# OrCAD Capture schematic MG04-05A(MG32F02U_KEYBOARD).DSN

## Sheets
1 01. Power Supply: size B; title: System Power; rev: 1.1; company: megawin; note: MG04-05
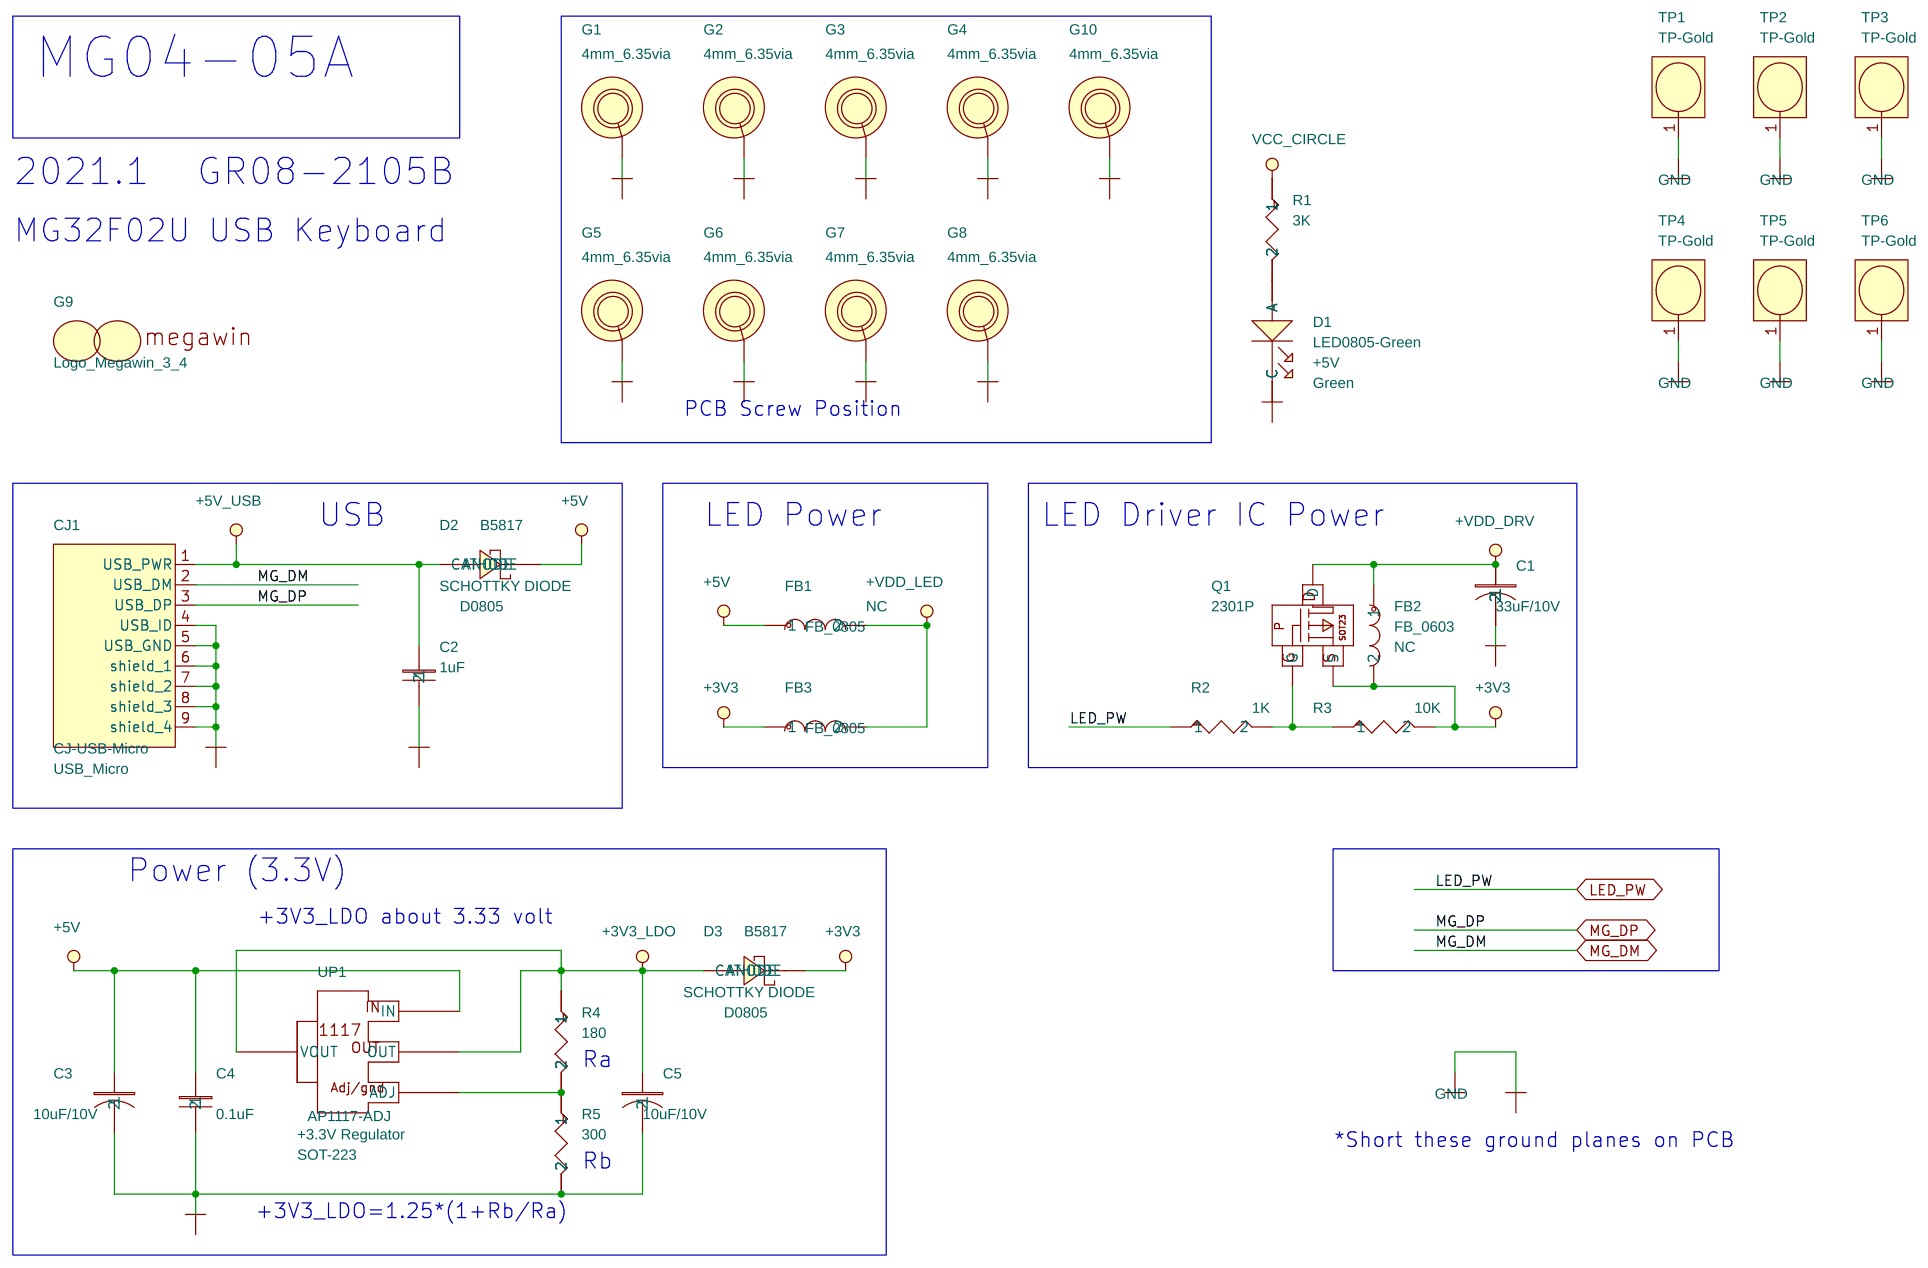
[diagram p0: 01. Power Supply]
2 02. Key Matrix: size Custom; title: Key Matrix; rev: 1.0
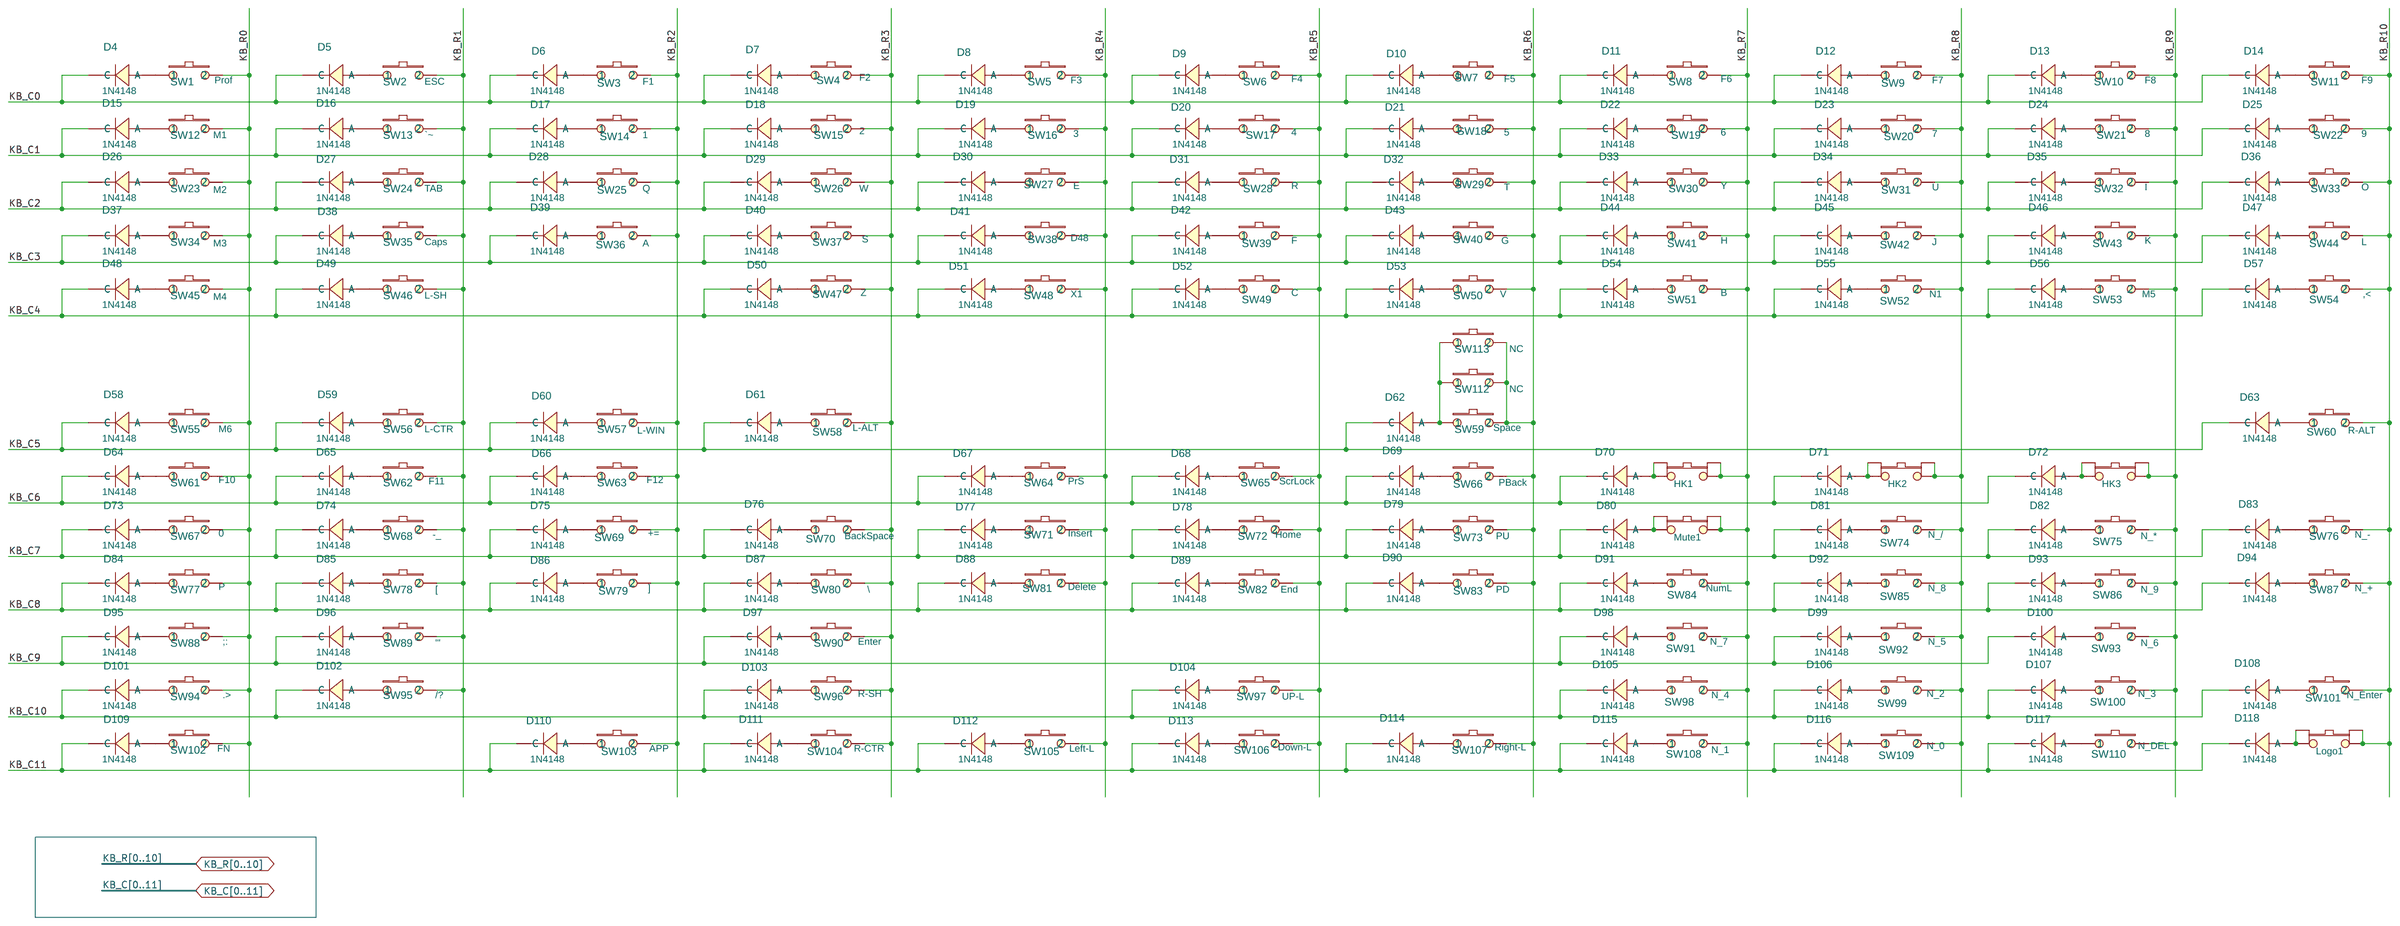
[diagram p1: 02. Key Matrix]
3 03. LED Matrix: size Custom; title: LED Matrix; rev: 1.0
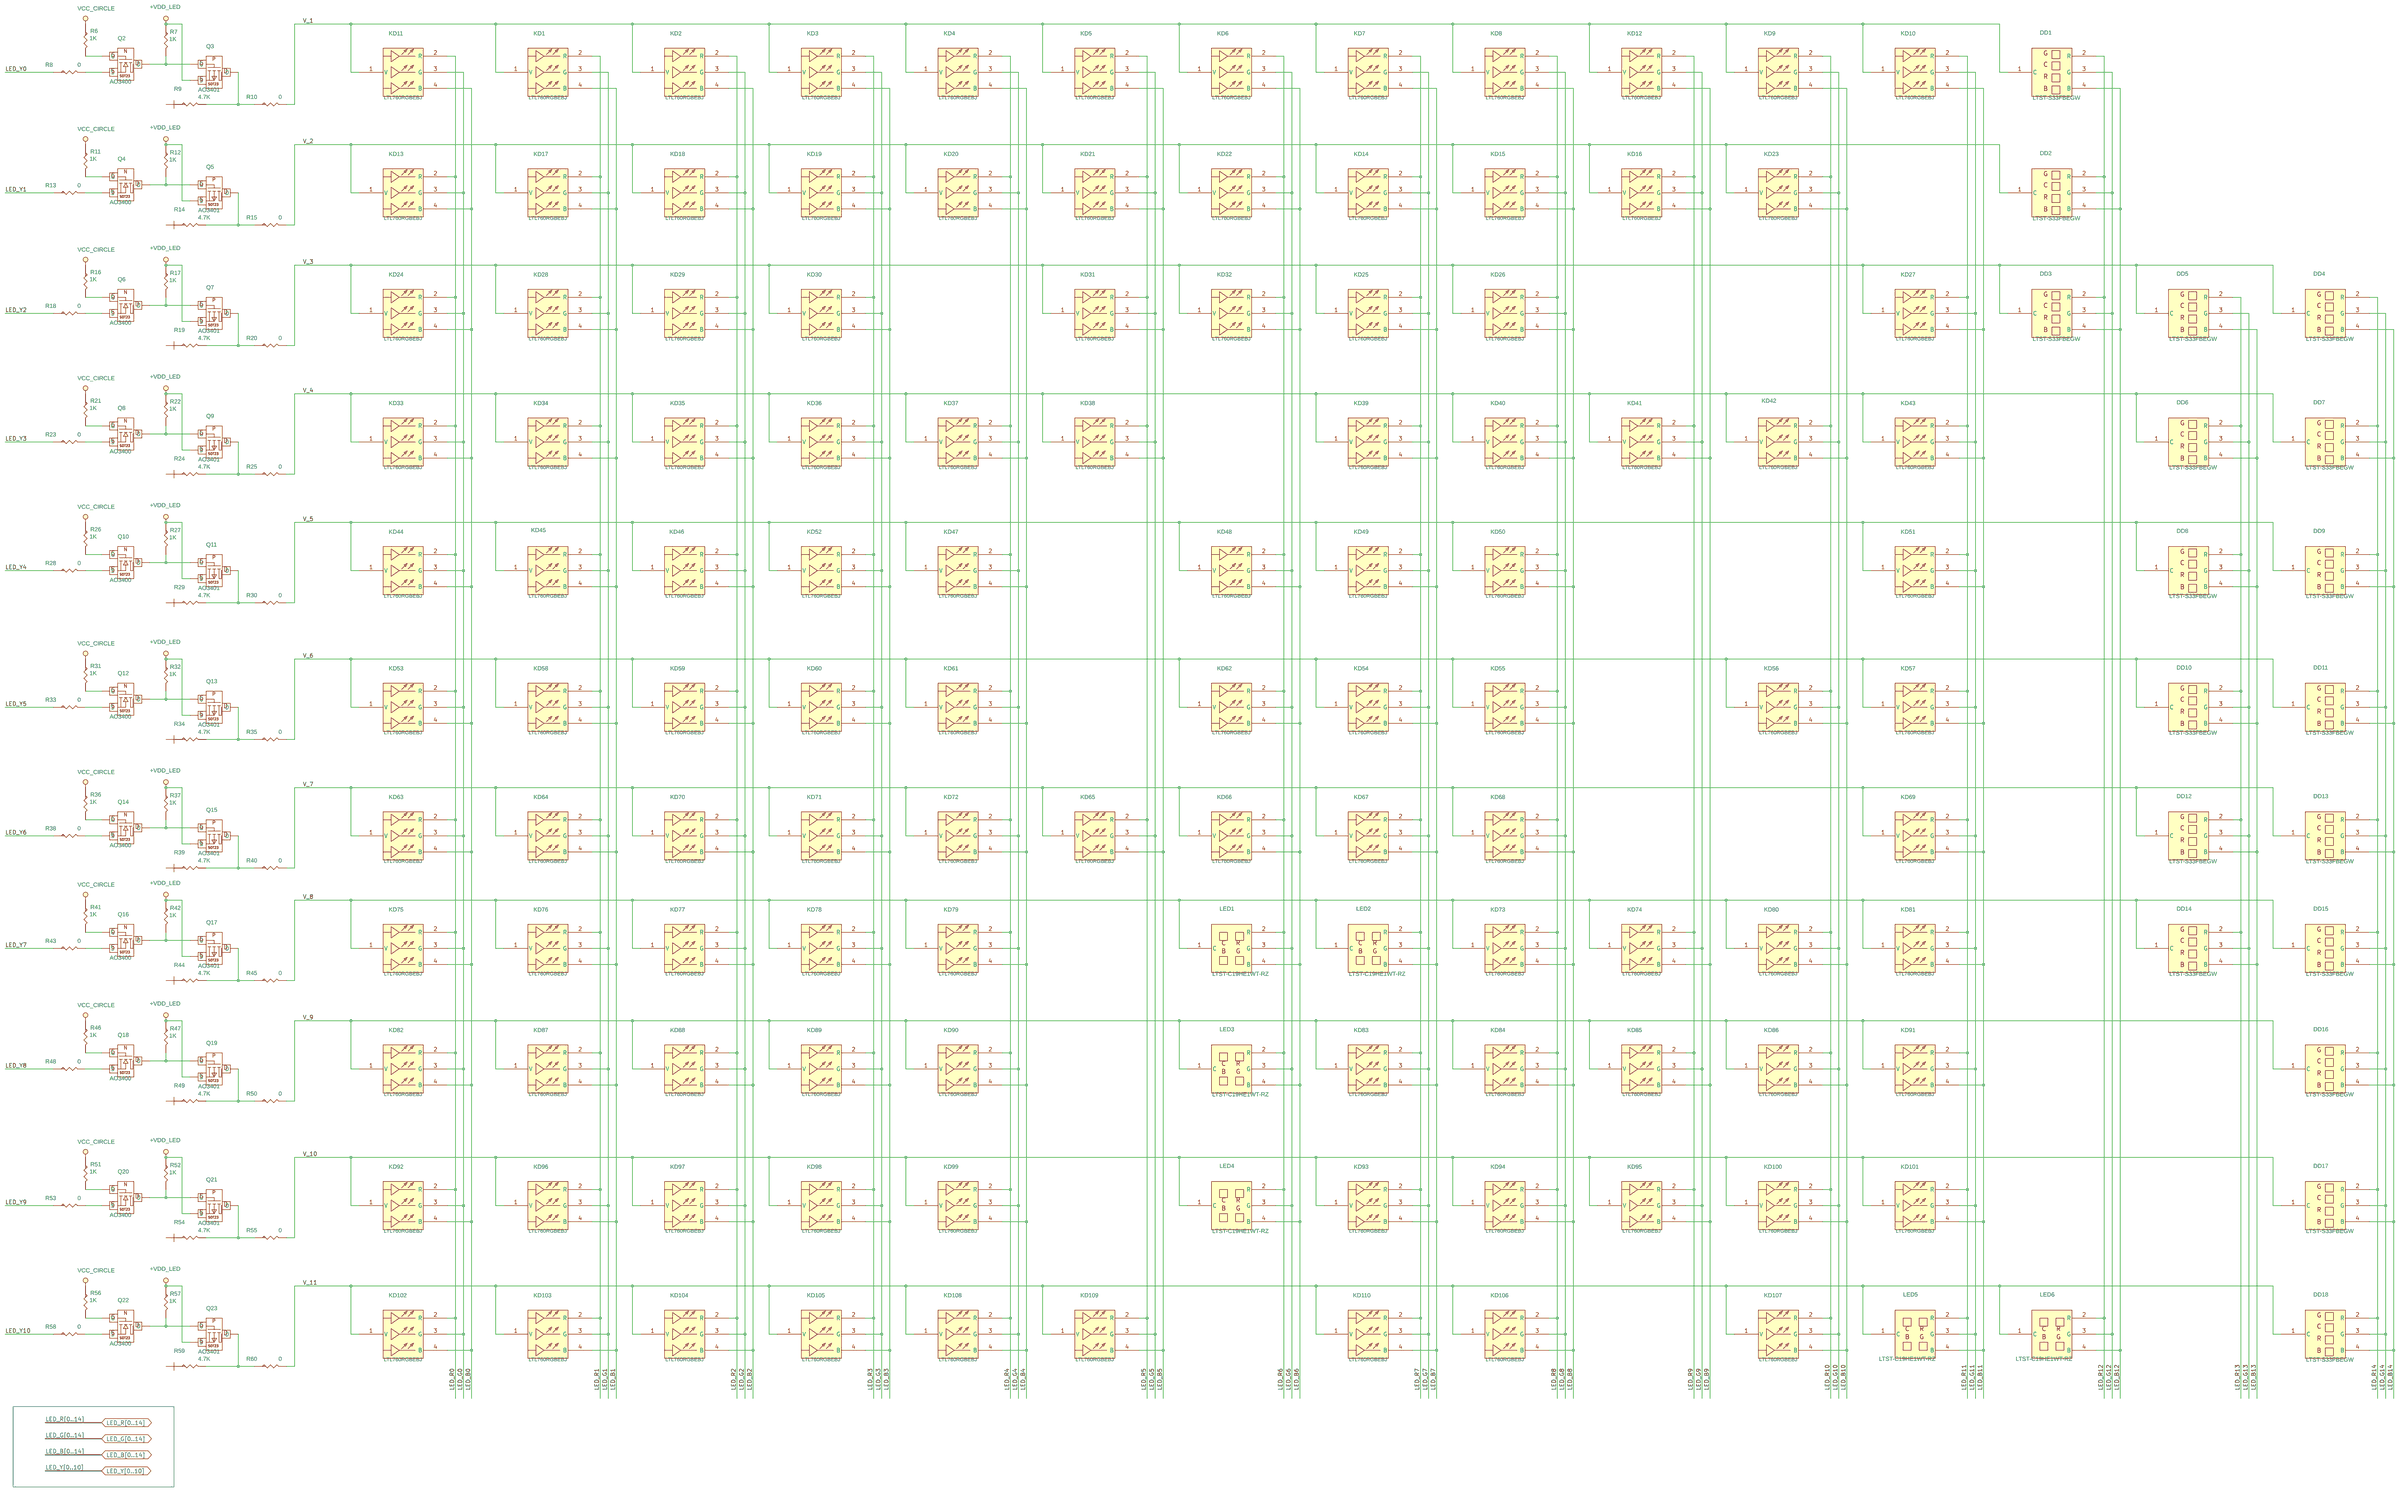
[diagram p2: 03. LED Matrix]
4 04. MCU IF: size Custom; title: MCU IF, LED Driver and Others
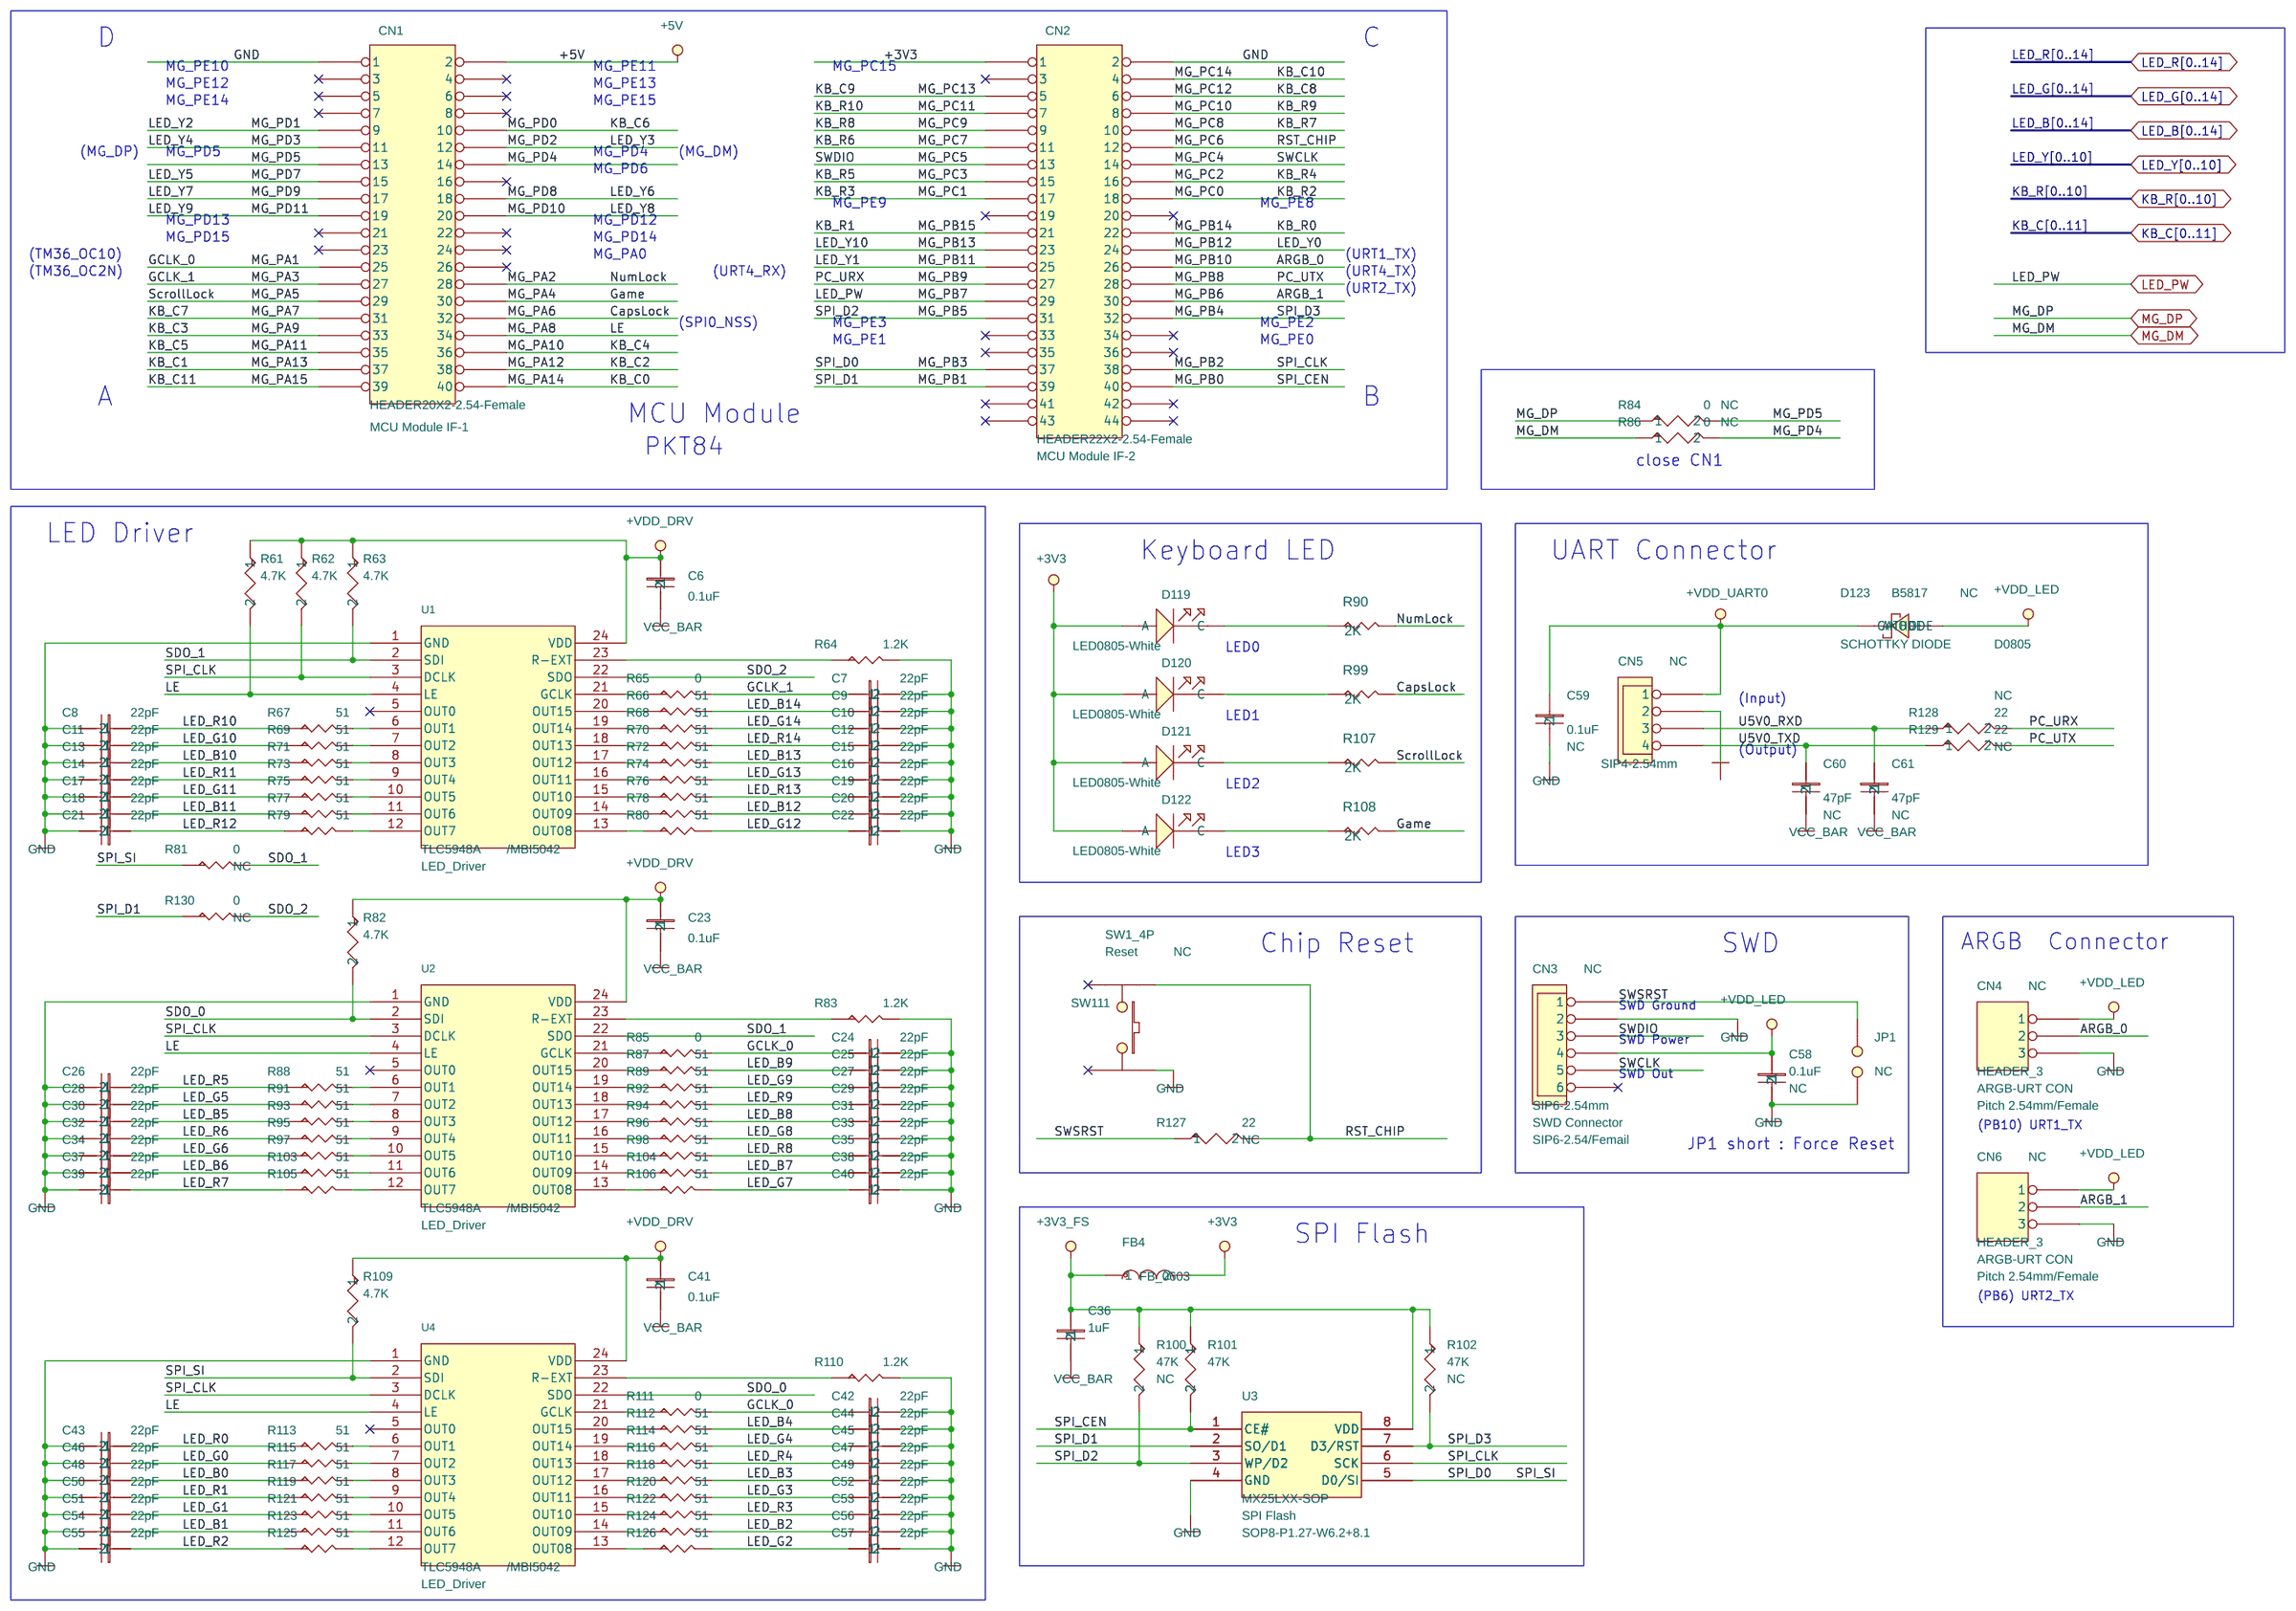
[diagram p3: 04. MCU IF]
5 20. Board Comment: title: Board Comment; rev: 1.0
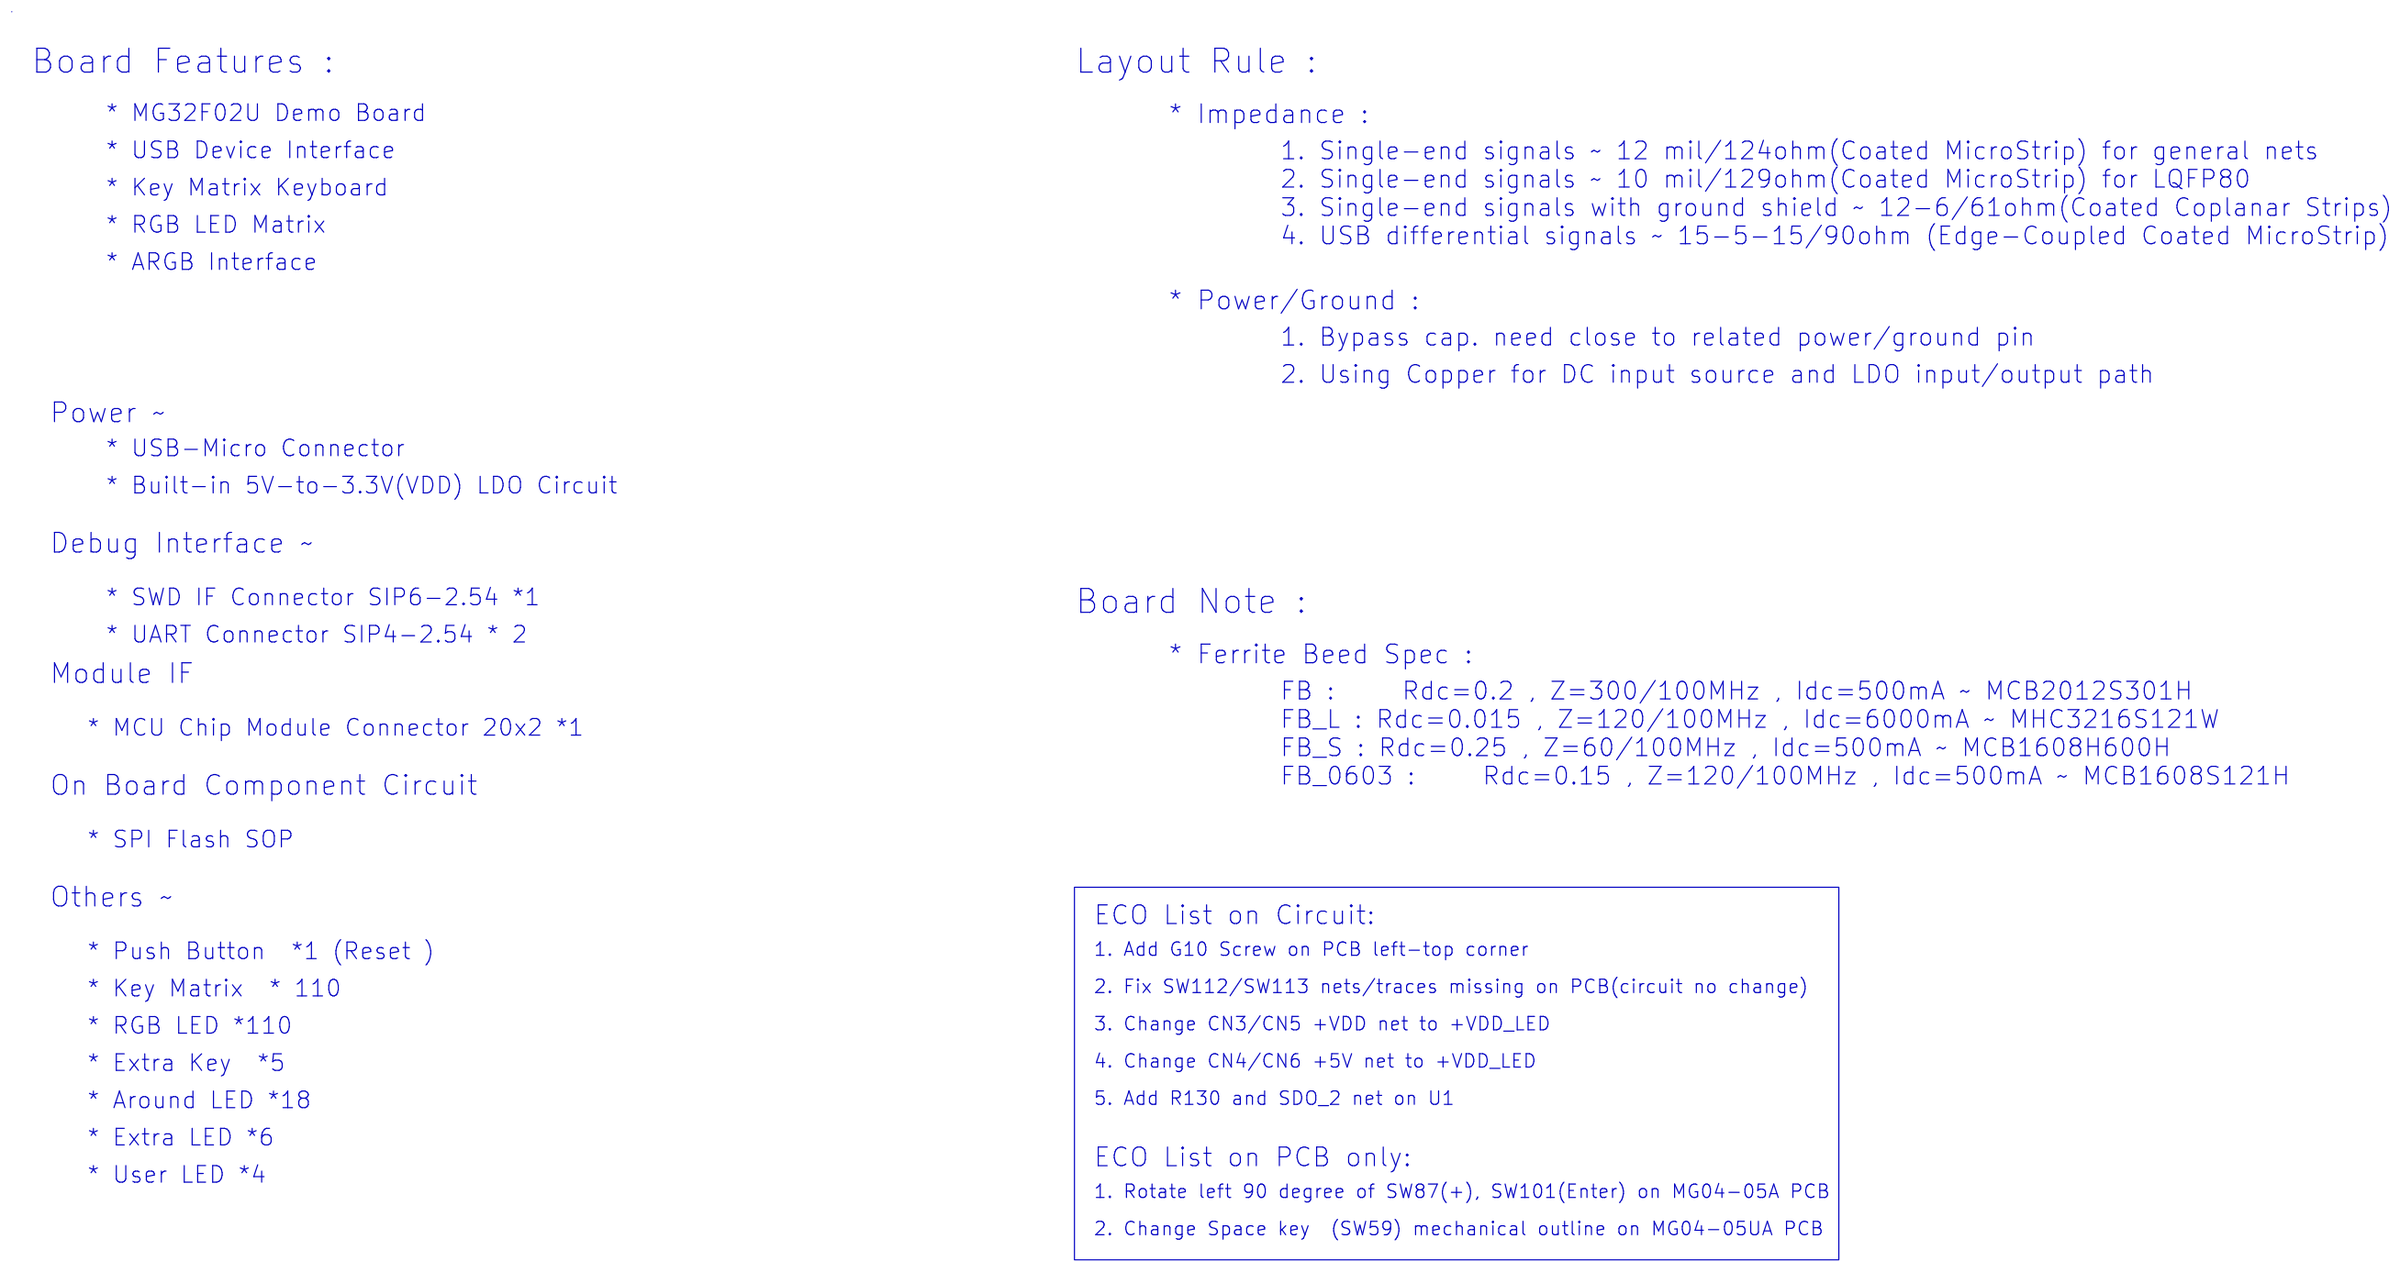
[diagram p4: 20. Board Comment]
6 21. PCB Placement: title: PCB Placement Plan; rev: 1.0
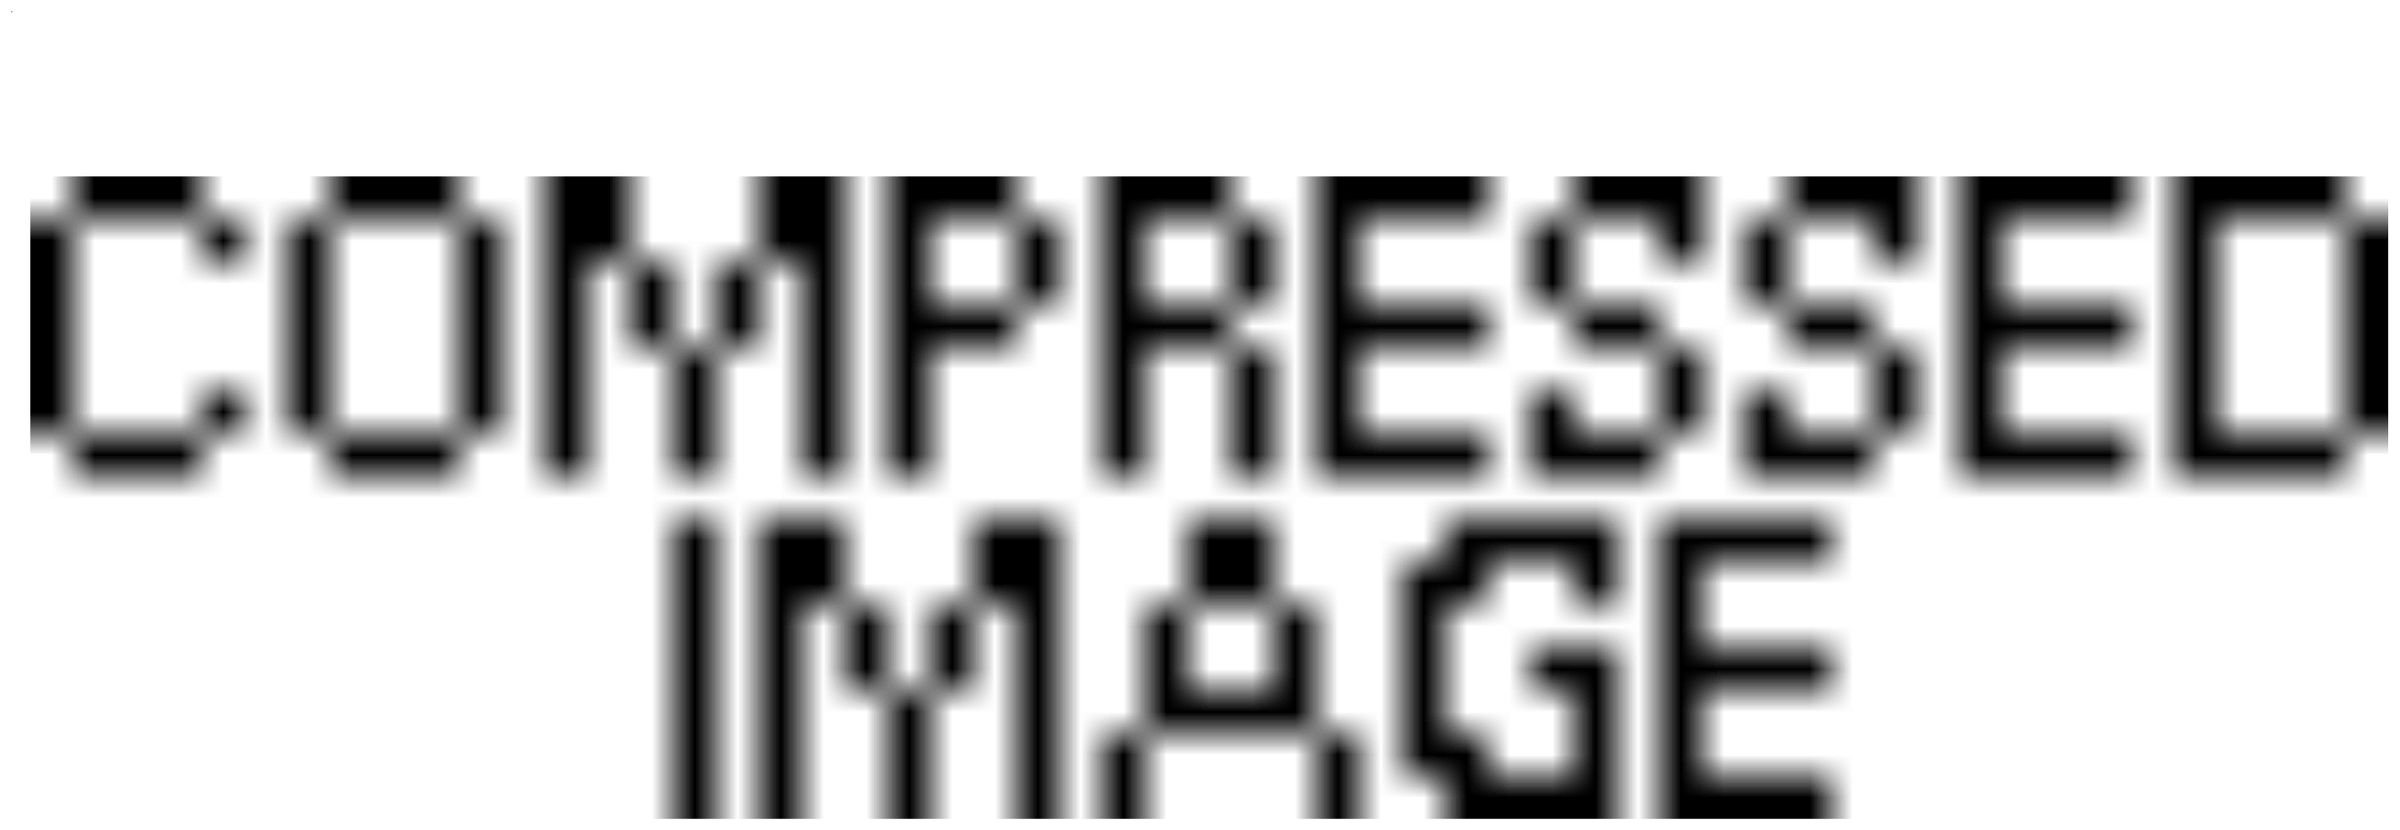
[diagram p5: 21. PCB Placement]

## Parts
sheet 01. Power Supply
C1  33uF/10V  [C-0805]
C2  1uF  [C-0603]
C3  10uF/10V  [C-0805]
C4  0.1uF  [C-0603]
C5  10uF/10V  [C-0805]
CJ1  CJ-USB-Micro  [USB5A-MICRO-290X220P065]
D1  LED0805-Green  [LED-0805]
D2  B5817  [D-0805]
D3  B5817  [D-0805]
FB1  FB_0805  [L-0805]
FB2  FB_0603  [L-0603]
FB3  FB_0805  [L-0805]
G1  4mm_6.35via  [SCREW1-H4-R6.35]
G2  4mm_6.35via  [SCREW1-H4-R6.35]
G3  4mm_6.35via  [SCREW1-H4-R6.35]
G4  4mm_6.35via  [SCREW1-H4-R6.35]
G5  4mm_6.35via  [SCREW1-H4-R6.35]
G6  4mm_6.35via  [SCREW1-H4-R6.35]
G7  4mm_6.35via  [SCREW1-H4-R6.35]
G8  4mm_6.35via  [SCREW1-H4-R6.35]
G9  Logo_Megawin_3_4  [MEGAWIN_3.4]
G10  4mm_6.35via  [SCREW1-H4-R6.35]
Q1  2301P  [SOT-23]
R1  3K  [R-0603]
R2  1K  [R-0603]
R3  10K  [R-0603]
R4  180  [R-0603]
R5  300  [R-0603]
TP1  TP-Gold  [SIP1-39]
TP2  TP-Gold  [SIP1-39]
TP3  TP-Gold  [SIP1-39]
TP4  TP-Gold  [SIP1-39]
TP5  TP-Gold  [SIP1-39]
TP6  TP-Gold  [SIP1-39]
UP1  AP1117-ADJ  [SOT223H\3P]
sheet 02. Key Matrix
D4  1N4148  [DIODE_DO213AA]
D5  1N4148  [DIODE_DO213AA]
D6  1N4148  [DIODE_DO213AA]
D7  1N4148  [DIODE_DO213AA]
D8  1N4148  [DIODE_DO213AA]
D9  1N4148  [DIODE_DO213AA]
D10  1N4148  [DIODE_DO213AA]
D11  1N4148  [DIODE_DO213AA]
D12  1N4148  [DIODE_DO213AA]
D13  1N4148  [DIODE_DO213AA]
D14  1N4148  [DIODE_DO213AA]
D15  1N4148  [DIODE_DO213AA]
D16  1N4148  [DIODE_DO213AA]
D17  1N4148  [DIODE_DO213AA]
D18  1N4148  [DIODE_DO213AA]
D19  1N4148  [DIODE_DO213AA]
D20  1N4148  [DIODE_DO213AA]
D21  1N4148  [DIODE_DO213AA]
D22  1N4148  [DIODE_DO213AA]
D23  1N4148  [DIODE_DO213AA]
D24  1N4148  [DIODE_DO213AA]
D25  1N4148  [DIODE_DO213AA]
D26  1N4148  [DIODE_DO213AA]
D27  1N4148  [DIODE_DO213AA]
D28  1N4148  [DIODE_DO213AA]
D29  1N4148  [DIODE_DO213AA]
D30  1N4148  [DIODE_DO213AA]
D31  1N4148  [DIODE_DO213AA]
D32  1N4148  [DIODE_DO213AA]
D33  1N4148  [DIODE_DO213AA]
D34  1N4148  [DIODE_DO213AA]
D35  1N4148  [DIODE_DO213AA]
D36  1N4148  [DIODE_DO213AA]
D37  1N4148  [DIODE_DO213AA]
D38  1N4148  [DIODE_DO213AA]
D39  1N4148  [DIODE_DO213AA]
D40  1N4148  [DIODE_DO213AA]
D41  1N4148  [DIODE_DO213AA]
D42  1N4148  [DIODE_DO213AA]
D43  1N4148  [DIODE_DO213AA]
D44  1N4148  [DIODE_DO213AA]
D45  1N4148  [DIODE_DO213AA]
D46  1N4148  [DIODE_DO213AA]
D47  1N4148  [DIODE_DO213AA]
D48  1N4148  [DIODE_DO213AA]
D49  1N4148  [DIODE_DO213AA]
D50  1N4148  [DIODE_DO213AA]
D51  1N4148  [DIODE_DO213AA]
D52  1N4148  [DIODE_DO213AA]
D53  1N4148  [DIODE_DO213AA]
D54  1N4148  [DIODE_DO213AA]
D55  1N4148  [DIODE_DO213AA]
D56  1N4148  [DIODE_DO213AA]
D57  1N4148  [DIODE_DO213AA]
D58  1N4148  [DIODE_DO213AA]
D59  1N4148  [DIODE_DO213AA]
D60  1N4148  [DIODE_DO213AA]
D61  1N4148  [DIODE_DO213AA]
D62  1N4148  [DIODE_DO213AA]
D63  1N4148  [DIODE_DO213AA]
D64  1N4148  [DIODE_DO213AA]
D65  1N4148  [DIODE_DO213AA]
D66  1N4148  [DIODE_DO213AA]
D67  1N4148  [DIODE_DO213AA]
D68  1N4148  [DIODE_DO213AA]
D69  1N4148  [DIODE_DO213AA]
D70  1N4148  [DIODE_DO213AA]
D71  1N4148  [DIODE_DO213AA]
D72  1N4148  [DIODE_DO213AA]
D73  1N4148  [DIODE_DO213AA]
D74  1N4148  [DIODE_DO213AA]
D75  1N4148  [DIODE_DO213AA]
D76  1N4148  [DIODE_DO213AA]
D77  1N4148  [DIODE_DO213AA]
D78  1N4148  [DIODE_DO213AA]
D79  1N4148  [DIODE_DO213AA]
D80  1N4148  [DIODE_DO213AA]
D81  1N4148  [DIODE_DO213AA]
D82  1N4148  [DIODE_DO213AA]
D83  1N4148  [DIODE_DO213AA]
D84  1N4148  [DIODE_DO213AA]
D85  1N4148  [DIODE_DO213AA]
D86  1N4148  [DIODE_DO213AA]
D87  1N4148  [DIODE_DO213AA]
D88  1N4148  [DIODE_DO213AA]
D89  1N4148  [DIODE_DO213AA]
D90  1N4148  [DIODE_DO213AA]
D91  1N4148  [DIODE_DO213AA]
D92  1N4148  [DIODE_DO213AA]
D93  1N4148  [DIODE_DO213AA]
D94  1N4148  [DIODE_DO213AA]
D95  1N4148  [DIODE_DO213AA]
D96  1N4148  [DIODE_DO213AA]
D97  1N4148  [DIODE_DO213AA]
D98  1N4148  [DIODE_DO213AA]
D99  1N4148  [DIODE_DO213AA]
D100  1N4148  [DIODE_DO213AA]
D101  1N4148  [DIODE_DO213AA]
D102  1N4148  [DIODE_DO213AA]
D103  1N4148  [DIODE_DO213AA]
D104  1N4148  [DIODE_DO213AA]
D105  1N4148  [DIODE_DO213AA]
D106  1N4148  [DIODE_DO213AA]
D107  1N4148  [DIODE_DO213AA]
D108  1N4148  [DIODE_DO213AA]
D109  1N4148  [DIODE_DO213AA]
D110  1N4148  [DIODE_DO213AA]
D111  1N4148  [DIODE_DO213AA]
D112  1N4148  [DIODE_DO213AA]
D113  1N4148  [DIODE_DO213AA]
D114  1N4148  [DIODE_DO213AA]
D115  1N4148  [DIODE_DO213AA]
D116  1N4148  [DIODE_DO213AA]
D117  1N4148  [DIODE_DO213AA]
D118  1N4148  [DIODE_DO213AA]
HK1  SW-PB-4P  [SW-TACT-P4.5X6.5-Z6.2X6.2X5]
HK2  SW-PB-4P  [SW-TACT-P4.5X6.5-Z6.2X6.2X5]
HK3  SW-PB-4P  [SW-TACT-P4.5X6.5-Z6.2X6.2X5]
Logo1  SW-PB-4P  [SW-TACT-P4.5X6.5-Z6.2X6.2X5]
Mute1  SW-PB-4P  [SW-TACT-P4.5X6.5-Z6.2X6.2X5]
SW1  SW_PB_SPST  [SW2_KS4B]
SW2  SW_PB_SPST  [SW2_KS4B]
SW3  SW_PB_SPST  [SW2_KS4B]
SW4  SW_PB_SPST  [SW2_KS4B]
SW5  SW_PB_SPST  [SW2_KS4B]
SW6  SW_PB_SPST  [SW2_KS4B]
SW7  SW_PB_SPST  [SW2_KS4B]
SW8  SW_PB_SPST  [SW2_KS4B]
SW9  SW_PB_SPST  [SW2_KS4B]
SW10  SW_PB_SPST  [SW2_KS4B]
SW11  SW_PB_SPST  [SW2_KS4B]
SW12  SW_PB_SPST  [SW2_KS4B]
SW13  SW_PB_SPST  [SW2_KS4B]
SW14  SW_PB_SPST  [SW2_KS4B]
SW15  SW_PB_SPST  [SW2_KS4B]
SW16  SW_PB_SPST  [SW2_KS4B]
SW17  SW_PB_SPST  [SW2_KS4B]
SW18  SW_PB_SPST  [SW2_KS4B]
SW19  SW_PB_SPST  [SW2_KS4B]
SW20  SW_PB_SPST  [SW2_KS4B]
SW21  SW_PB_SPST  [SW2_KS4B]
SW22  SW_PB_SPST  [SW2_KS4B]
SW23  SW_PB_SPST  [SW2_KS4B]
SW24  SW_PB_SPST  [SW2_KS4B]
SW25  SW_PB_SPST  [SW2_KS4B]
SW26  SW_PB_SPST  [SW2_KS4B]
SW27  SW_PB_SPST  [SW2_KS4B]
SW28  SW_PB_SPST  [SW2_KS4B]
SW29  SW_PB_SPST  [SW2_KS4B]
SW30  SW_PB_SPST  [SW2_KS4B]
SW31  SW_PB_SPST  [SW2_KS4B]
SW32  SW_PB_SPST  [SW2_KS4B]
SW33  SW_PB_SPST  [SW2_KS4B]
SW34  SW_PB_SPST  [SW2_KS4B]
SW35  SW_PB_SPST  [SW2_KS4B]
SW36  SW_PB_SPST  [SW2_KS4B]
SW37  SW_PB_SPST  [SW2_KS4B]
SW38  SW_PB_SPST  [SW2_KS4B]
SW39  SW_PB_SPST  [SW2_KS4B]
SW40  SW_PB_SPST  [SW2_KS4B]
SW41  SW_PB_SPST  [SW2_KS4B]
SW42  SW_PB_SPST  [SW2_KS4B]
SW43  SW_PB_SPST  [SW2_KS4B]
SW44  SW_PB_SPST  [SW2_KS4B]
SW45  SW_PB_SPST  [SW2_KS4B]
SW46  SW_PB_SPST  [SW2_KS4B]
SW47  SW_PB_SPST  [SW2_KS4B]
SW48  SW_PB_SPST  [SW2_KS4B]
SW49  SW_PB_SPST  [SW2_KS4B]
SW50  SW_PB_SPST  [SW2_KS4B]
SW51  SW_PB_SPST  [SW2_KS4B]
SW52  SW_PB_SPST  [SW2_KS4B]
SW53  SW_PB_SPST  [SW2_KS4B]
SW54  SW_PB_SPST  [SW2_KS4B]
SW55  SW_PB_SPST  [SW2_KS4B]
SW56  SW_PB_SPST  [SW2_KS4B]
SW57  SW_PB_SPST  [SW2_KS4B]
SW58  SW_PB_SPST  [SW2_KS4B]
SW59  SW_PB_SPST  [SW2_KS4B]
SW60  SW_PB_SPST  [SW2_KS4B]
SW61  SW_PB_SPST  [SW2_KS4B]
SW62  SW_PB_SPST  [SW2_KS4B]
SW63  SW_PB_SPST  [SW2_KS4B]
SW64  SW_PB_SPST  [SW2_KS4B]
SW65  SW_PB_SPST  [SW2_KS4B]
SW66  SW_PB_SPST  [SW2_KS4B]
SW67  SW_PB_SPST  [SW2_KS4B]
SW68  SW_PB_SPST  [SW2_KS4B]
SW69  SW_PB_SPST  [SW2_KS4B]
SW70  SW_PB_SPST  [SW2_KS4B]
SW71  SW_PB_SPST  [SW2_KS4B]
SW72  SW_PB_SPST  [SW2_KS4B]
SW73  SW_PB_SPST  [SW2_KS4B]
SW74  SW_PB_SPST  [SW2_KS4B]
SW75  SW_PB_SPST  [SW2_KS4B]
SW76  SW_PB_SPST  [SW2_KS4B]
SW77  SW_PB_SPST  [SW2_KS4B]
SW78  SW_PB_SPST  [SW2_KS4B]
SW79  SW_PB_SPST  [SW2_KS4B]
SW80  SW_PB_SPST  [SW2_KS4B]
SW81  SW_PB_SPST  [SW2_KS4B]
SW82  SW_PB_SPST  [SW2_KS4B]
SW83  SW_PB_SPST  [SW2_KS4B]
SW84  SW_PB_SPST  [SW2_KS4B]
SW85  SW_PB_SPST  [SW2_KS4B]
SW86  SW_PB_SPST  [SW2_KS4B]
SW87  SW_PB_SPST  [SW2_KS4B]
SW88  SW_PB_SPST  [SW2_KS4B]
SW89  SW_PB_SPST  [SW2_KS4B]
SW90  SW_PB_SPST  [SW2_KS4B]
SW91  SW_PB_SPST  [SW2_KS4B]
SW92  SW_PB_SPST  [SW2_KS4B]
SW93  SW_PB_SPST  [SW2_KS4B]
SW94  SW_PB_SPST  [SW2_KS4B]
SW95  SW_PB_SPST  [SW2_KS4B]
SW96  SW_PB_SPST  [SW2_KS4B]
SW97  SW_PB_SPST  [SW2_KS4B]
SW98  SW_PB_SPST  [SW2_KS4B]
SW99  SW_PB_SPST  [SW2_KS4B]
SW100  SW_PB_SPST  [SW2_KS4B]
SW101  SW_PB_SPST  [SW2_KS4B]
SW102  SW_PB_SPST  [SW2_KS4B]
SW103  SW_PB_SPST  [SW2_KS4B]
SW104  SW_PB_SPST  [SW2_KS4B]
SW105  SW_PB_SPST  [SW2_KS4B]
SW106  SW_PB_SPST  [SW2_KS4B]
SW107  SW_PB_SPST  [SW2_KS4B]
SW108  SW_PB_SPST  [SW2_KS4B]
SW109  SW_PB_SPST  [SW2_KS4B]
SW110  SW_PB_SPST  [SW2_KS4B]
SW112  SW_PB_SPST  [SW2_KS4B]
SW113  SW_PB_SPST  [SW2_KS4B]
sheet 03. LED Matrix
DD1  LTST-S33FBEGW  [LED4P_SMD_3X1_CRGB]
DD2  LTST-S33FBEGW  [LED4P_SMD_3X1_CRGB]
DD3  LTST-S33FBEGW  [LED4P_SMD_3X1_CRGB]
DD4  LTST-S33FBEGW  [LED4P_SMD_3X1_CRGB]
DD5  LTST-S33FBEGW  [LED4P_SMD_3X1_CRGB]
DD6  LTST-S33FBEGW  [LED4P_SMD_3X1_CRGB]
DD7  LTST-S33FBEGW  [LED4P_SMD_3X1_CRGB]
DD8  LTST-S33FBEGW  [LED4P_SMD_3X1_CRGB]
DD9  LTST-S33FBEGW  [LED4P_SMD_3X1_CRGB]
DD10  LTST-S33FBEGW  [LED4P_SMD_3X1_CRGB]
DD11  LTST-S33FBEGW  [LED4P_SMD_3X1_CRGB]
DD12  LTST-S33FBEGW  [LED4P_SMD_3X1_CRGB]
DD13  LTST-S33FBEGW  [LED4P_SMD_3X1_CRGB]
DD14  LTST-S33FBEGW  [LED4P_SMD_3X1_CRGB]
DD15  LTST-S33FBEGW  [LED4P_SMD_3X1_CRGB]
DD16  LTST-S33FBEGW  [LED4P_SMD_3X1_CRGB]
DD17  LTST-S33FBEGW  [LED4P_SMD_3X1_CRGB]
DD18  LTST-S33FBEGW  [LED4P_SMD_3X1_CRGB]
KD1  LTL760RGBEBJ  [LED_3.5_CRGB]
KD2  LTL760RGBEBJ  [LED_3.5_CRGB]
KD3  LTL760RGBEBJ  [LED_3.5_CRGB]
KD4  LTL760RGBEBJ  [LED_3.5_CRGB]
KD5  LTL760RGBEBJ  [LED_3.5_CRGB]
KD6  LTL760RGBEBJ  [LED_3.5_CRGB]
KD7  LTL760RGBEBJ  [LED_3.5_CRGB]
KD8  LTL760RGBEBJ  [LED_3.5_CRGB]
KD9  LTL760RGBEBJ  [LED_3.5_CRGB]
KD10  LTL760RGBEBJ  [LED_3.5_CRGB]
KD11  LTL760RGBEBJ  [LED_3.5_CRGB]
KD12  LTL760RGBEBJ  [LED_3.5_CRGB]
KD13  LTL760RGBEBJ  [LED_3.5_CRGB]
KD14  LTL760RGBEBJ  [LED_3.5_CRGB]
KD15  LTL760RGBEBJ  [LED_3.5_CRGB]
KD16  LTL760RGBEBJ  [LED_3.5_CRGB]
KD17  LTL760RGBEBJ  [LED_3.5_CRGB]
KD18  LTL760RGBEBJ  [LED_3.5_CRGB]
KD19  LTL760RGBEBJ  [LED_3.5_CRGB]
KD20  LTL760RGBEBJ  [LED_3.5_CRGB]
KD21  LTL760RGBEBJ  [LED_3.5_CRGB]
KD22  LTL760RGBEBJ  [LED_3.5_CRGB]
KD23  LTL760RGBEBJ  [LED_3.5_CRGB]
KD24  LTL760RGBEBJ  [LED_3.5_CRGB]
KD25  LTL760RGBEBJ  [LED_3.5_CRGB]
KD26  LTL760RGBEBJ  [LED_3.5_CRGB]
KD27  LTL760RGBEBJ  [LED_3.5_CRGB]
KD28  LTL760RGBEBJ  [LED_3.5_CRGB]
KD29  LTL760RGBEBJ  [LED_3.5_CRGB]
KD30  LTL760RGBEBJ  [LED_3.5_CRGB]
KD31  LTL760RGBEBJ  [LED_3.5_CRGB]
KD32  LTL760RGBEBJ  [LED_3.5_CRGB]
KD33  LTL760RGBEBJ  [LED_3.5_CRGB]
KD34  LTL760RGBEBJ  [LED_3.5_CRGB]
KD35  LTL760RGBEBJ  [LED_3.5_CRGB]
KD36  LTL760RGBEBJ  [LED_3.5_CRGB]
KD37  LTL760RGBEBJ  [LED_3.5_CRGB]
KD38  LTL760RGBEBJ  [LED_3.5_CRGB]
KD39  LTL760RGBEBJ  [LED_3.5_CRGB]
KD40  LTL760RGBEBJ  [LED_3.5_CRGB]
KD41  LTL760RGBEBJ  [LED_3.5_CRGB]
KD42  LTL760RGBEBJ  [LED_3.5_CRGB]
KD43  LTL760RGBEBJ  [LED_3.5_CRGB]
KD44  LTL760RGBEBJ  [LED_3.5_CRGB]
KD45  LTL760RGBEBJ  [LED_3.5_CRGB]
KD46  LTL760RGBEBJ  [LED_3.5_CRGB]
KD47  LTL760RGBEBJ  [LED_3.5_CRGB]
KD48  LTL760RGBEBJ  [LED_3.5_CRGB]
KD49  LTL760RGBEBJ  [LED_3.5_CRGB]
KD50  LTL760RGBEBJ  [LED_3.5_CRGB]
KD51  LTL760RGBEBJ  [LED_3.5_CRGB]
KD52  LTL760RGBEBJ  [LED_3.5_CRGB]
KD53  LTL760RGBEBJ  [LED_3.5_CRGB]
KD54  LTL760RGBEBJ  [LED_3.5_CRGB]
KD55  LTL760RGBEBJ  [LED_3.5_CRGB]
KD56  LTL760RGBEBJ  [LED_3.5_CRGB]
KD57  LTL760RGBEBJ  [LED_3.5_CRGB]
KD58  LTL760RGBEBJ  [LED_3.5_CRGB]
KD59  LTL760RGBEBJ  [LED_3.5_CRGB]
KD60  LTL760RGBEBJ  [LED_3.5_CRGB]
KD61  LTL760RGBEBJ  [LED_3.5_CRGB]
KD62  LTL760RGBEBJ  [LED_3.5_CRGB]
KD63  LTL760RGBEBJ  [LED_3.5_CRGB]
KD64  LTL760RGBEBJ  [LED_3.5_CRGB]
KD65  LTL760RGBEBJ  [LED_3.5_CRGB]
KD66  LTL760RGBEBJ  [LED_3.5_CRGB]
KD67  LTL760RGBEBJ  [LED_3.5_CRGB]
KD68  LTL760RGBEBJ  [LED_3.5_CRGB]
KD69  LTL760RGBEBJ  [LED_3.5_CRGB]
KD70  LTL760RGBEBJ  [LED_3.5_CRGB]
KD71  LTL760RGBEBJ  [LED_3.5_CRGB]
KD72  LTL760RGBEBJ  [LED_3.5_CRGB]
KD73  LTL760RGBEBJ  [LED_3.5_CRGB]
KD74  LTL760RGBEBJ  [LED_3.5_CRGB]
KD75  LTL760RGBEBJ  [LED_3.5_CRGB]
KD76  LTL760RGBEBJ  [LED_3.5_CRGB]
KD77  LTL760RGBEBJ  [LED_3.5_CRGB]
KD78  LTL760RGBEBJ  [LED_3.5_CRGB]
KD79  LTL760RGBEBJ  [LED_3.5_CRGB]
KD80  LTL760RGBEBJ  [LED_3.5_CRGB]
KD81  LTL760RGBEBJ  [LED_3.5_CRGB]
KD82  LTL760RGBEBJ  [LED_3.5_CRGB]
KD83  LTL760RGBEBJ  [LED_3.5_CRGB]
KD84  LTL760RGBEBJ  [LED_3.5_CRGB]
KD85  LTL760RGBEBJ  [LED_3.5_CRGB]
KD86  LTL760RGBEBJ  [LED_3.5_CRGB]
KD87  LTL760RGBEBJ  [LED_3.5_CRGB]
KD88  LTL760RGBEBJ  [LED_3.5_CRGB]
KD89  LTL760RGBEBJ  [LED_3.5_CRGB]
KD90  LTL760RGBEBJ  [LED_3.5_CRGB]
KD91  LTL760RGBEBJ  [LED_3.5_CRGB]
KD92  LTL760RGBEBJ  [LED_3.5_CRGB]
KD93  LTL760RGBEBJ  [LED_3.5_CRGB]
KD94  LTL760RGBEBJ  [LED_3.5_CRGB]
KD95  LTL760RGBEBJ  [LED_3.5_CRGB]
KD96  LTL760RGBEBJ  [LED_3.5_CRGB]
KD97  LTL760RGBEBJ  [LED_3.5_CRGB]
KD98  LTL760RGBEBJ  [LED_3.5_CRGB]
KD99  LTL760RGBEBJ  [LED_3.5_CRGB]
KD100  LTL760RGBEBJ  [LED_3.5_CRGB]
KD101  LTL760RGBEBJ  [LED_3.5_CRGB]
KD102  LTL760RGBEBJ  [LED_3.5_CRGB]
KD103  LTL760RGBEBJ  [LED_3.5_CRGB]
KD104  LTL760RGBEBJ  [LED_3.5_CRGB]
KD105  LTL760RGBEBJ  [LED_3.5_CRGB]
KD106  LTL760RGBEBJ  [LED_3.5_CRGB]
KD107  LTL760RGBEBJ  [LED_3.5_CRGB]
KD108  LTL760RGBEBJ  [LED_3.5_CRGB]
KD109  LTL760RGBEBJ  [LED_3.5_CRGB]
KD110  LTL760RGBEBJ  [LED_3.5_CRGB]
LED1  LTST-C19HE1WT-RZ  [LED4P_SMD_1.6X1.6_CRGB]
LED2  LTST-C19HE1WT-RZ  [LED4P_SMD_1.6X1.6_CRGB]
LED3  LTST-C19HE1WT-RZ  [LED4P_SMD_1.6X1.6_CRGB]
LED4  LTST-C19HE1WT-RZ  [LED4P_SMD_1.6X1.6_CRGB]
LED5  LTST-C19HE1WT-RZ  [LED4P_SMD_1.6X1.6_CRGB]
LED6  LTST-C19HE1WT-RZ  [LED4P_SMD_1.6X1.6_CRGB]
Q2  AO3400  [SOT-23]
Q3  AO3401  [SOT-23]
Q4  AO3400  [SOT-23]
Q5  AO3401  [SOT-23]
Q6  AO3400  [SOT-23]
Q7  AO3401  [SOT-23]
Q8  AO3400  [SOT-23]
Q9  AO3401  [SOT-23]
Q10  AO3400  [SOT-23]
Q11  AO3401  [SOT-23]
Q12  AO3400  [SOT-23]
Q13  AO3401  [SOT-23]
Q14  AO3400  [SOT-23]
Q15  AO3401  [SOT-23]
Q16  AO3400  [SOT-23]
Q17  AO3401  [SOT-23]
Q18  AO3400  [SOT-23]
Q19  AO3401  [SOT-23]
Q20  AO3400  [SOT-23]
Q21  AO3401  [SOT-23]
Q22  AO3400  [SOT-23]
Q23  AO3401  [SOT-23]
R6  1K  [R-0603]
R7  1K  [R-0603]
R8  0  [R-0603]
R9  4.7K  [R-0603]
R10  0  [R-0603]
R11  1K  [R-0603]
R12  1K  [R-0603]
R13  0  [R-0603]
R14  4.7K  [R-0603]
R15  0  [R-0603]
R16  1K  [R-0603]
R17  1K  [R-0603]
R18  0  [R-0603]
R19  4.7K  [R-0603]
R20  0  [R-0603]
R21  1K  [R-0603]
R22  1K  [R-0603]
R23  0  [R-0603]
R24  4.7K  [R-0603]
R25  0  [R-0603]
R26  1K  [R-0603]
R27  1K  [R-0603]
R28  0  [R-0603]
R29  4.7K  [R-0603]
R30  0  [R-0603]
R31  1K  [R-0603]
R32  1K  [R-0603]
R33  0  [R-0603]
R34  4.7K  [R-0603]
R35  0  [R-0603]
R36  1K  [R-0603]
R37  1K  [R-0603]
R38  0  [R-0603]
R39  4.7K  [R-0603]
R40  0  [R-0603]
R41  1K  [R-0603]
R42  1K  [R-0603]
R43  0  [R-0603]
R44  4.7K  [R-0603]
R45  0  [R-0603]
R46  1K  [R-0603]
R47  1K  [R-0603]
R48  0  [R-0603]
R49  4.7K  [R-0603]
R50  0  [R-0603]
R51  1K  [R-0603]
R52  1K  [R-0603]
R53  0  [R-0603]
R54  4.7K  [R-0603]
R55  0  [R-0603]
R56  1K  [R-0603]
R57  1K  [R-0603]
R58  0  [R-0603]
R59  4.7K  [R-0603]
R60  0  [R-0603]
sheet 04. MCU IF
C6  0.1uF  [C-0603]
C7  22pF  [C-0603]
C8  22pF  [C-0603]
C9  22pF  [C-0603]
C10  22pF  [C-0603]
C11  22pF  [C-0603]
C12  22pF  [C-0603]
C13  22pF  [C-0603]
C14  22pF  [C-0603]
C15  22pF  [C-0603]
C16  22pF  [C-0603]
C17  22pF  [C-0603]
C18  22pF  [C-0603]
C19  22pF  [C-0603]
C20  22pF  [C-0603]
C21  22pF  [C-0603]
C22  22pF  [C-0603]
C23  0.1uF  [C-0603]
C24  22pF  [C-0603]
C25  22pF  [C-0603]
C26  22pF  [C-0603]
C27  22pF  [C-0603]
C28  22pF  [C-0603]
C29  22pF  [C-0603]
C30  22pF  [C-0603]
C31  22pF  [C-0603]
C32  22pF  [C-0603]
C33  22pF  [C-0603]
C34  22pF  [C-0603]
C35  22pF  [C-0603]
C36  1uF  [C-0603]
C37  22pF  [C-0603]
C38  22pF  [C-0603]
C39  22pF  [C-0603]
C40  22pF  [C-0603]
C41  0.1uF  [C-0603]
C42  22pF  [C-0603]
C43  22pF  [C-0603]
C44  22pF  [C-0603]
C45  22pF  [C-0603]
C46  22pF  [C-0603]
C47  22pF  [C-0603]
C48  22pF  [C-0603]
C49  22pF  [C-0603]
C50  22pF  [C-0603]
C51  22pF  [C-0603]
C52  22pF  [C-0603]
C53  22pF  [C-0603]
C54  22pF  [C-0603]
C55  22pF  [C-0603]
C56  22pF  [C-0603]
C57  22pF  [C-0603]
C58  0.1uF  [C-0603]
C59  0.1uF  [C-0603]
C60  47pF  [C-0603]
C61  47pF  [C-0603]
CN1  HEADER20X2-2.54-Female  [HD20X2-P2.54]
CN2  HEADER22X2-2.54-Female  [HD22X2-P2.54]
CN3  SIP6-2.54mm  [HD6-P2.54-UL]
CN4  HEADER_3  [SIP3-P2.54]
CN5  SIP4-2.54mm  [HD4-P2.54-Z12.4X5.7X7-UL]
CN6  HEADER_3  [SIP3-P2.54]
D119  LED0805-White  [LED-0805]
D120  LED0805-White  [LED-0805]
D121  LED0805-White  [LED-0805]
D122  LED0805-White  [LED-0805]
D123  B5817  [D-0805]
FB4  FB_0603  [L-0603]
JP1  JUMPER  [SIP2-P2.54]
R61  4.7K  [R-0603]
R62  4.7K  [R-0603]
R63  4.7K  [R-0603]
R64  1.2K  [R-0603]
R65  0  [R-0603]
R66  51  [R-0603]
R67  51  [R-0603]
R68  51  [R-0603]
R69  51  [R-0603]
R70  51  [R-0603]
R71  51  [R-0603]
R72  51  [R-0603]
R73  51  [R-0603]
R74  51  [R-0603]
R75  51  [R-0603]
R76  51  [R-0603]
R77  51  [R-0603]
R78  51  [R-0603]
R79  51  [R-0603]
R80  51  [R-0603]
R81  0  [R-0603]
R82  4.7K  [R-0603]
R83  1.2K  [R-0603]
R84  0  [R-0603]
R85  0  [R-0603]
R86  0  [R-0603]
R87  51  [R-0603]
R88  51  [R-0603]
R89  51  [R-0603]
R90  2K  [R-0603]
R91  51  [R-0603]
R92  51  [R-0603]
R93  51  [R-0603]
R94  51  [R-0603]
R95  51  [R-0603]
R96  51  [R-0603]
R97  51  [R-0603]
R98  51  [R-0603]
R99  2K  [R-0603]
R100  47K  [R-0603]
R101  47K  [R-0603]
R102  47K  [R-0603]
R103  51  [R-0603]
R104  51  [R-0603]
R105  51  [R-0603]
R106  51  [R-0603]
R107  2K  [R-0603]
R108  2K  [R-0603]
R109  4.7K  [R-0603]
R110  1.2K  [R-0603]
R111  0  [R-0603]
R112  51  [R-0603]
R113  51  [R-0603]
R114  51  [R-0603]
R115  51  [R-0603]
R116  51  [R-0603]
R117  51  [R-0603]
R118  51  [R-0603]
R119  51  [R-0603]
R120  51  [R-0603]
R121  51  [R-0603]
R122  51  [R-0603]
R123  51  [R-0603]
R124  51  [R-0603]
R125  51  [R-0603]
R126  51  [R-0603]
R127  22  [R-0603]
R128  22  [R-0603]
R129  22  [R-0603]
R130  0  [R-0603]
SW111  SW1_4P  [SW-TACT-P4.5X6.5-Z6.2X6.2X5]
U1  TLC5948A  [SOP24-P0.65-W6.4-PAD]
U2  TLC5948A  [SOP24-P0.65-W6.4-PAD]
U3  MX25LXX-SOP  [SOP8-P1.27-W6.2+8.1]
U4  TLC5948A  [SOP24-P0.65-W6.4-PAD]

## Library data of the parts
C1 = CAP-POL_1: Package: 1008 Multilayer Ceramic Chip Capacitor
C2 = CAP-NP: 2ND PART FIELD: SMD_0805; Package: 0603 Multilayer Ceramic Chip Capacitor
C3 = CAP-POL_2
C4 = CAP-NP_1
C5 = CAP-POL: Package: 1008 Multilayer Ceramic Chip Capacitor
CJ1 = CJ-USB-Micro: Package: USB_Micro
D1 = LED: Assembly: Green; Function: +5V; Package: Red
D2 D3 = DIODE-SCHOTTKY-2: Function: SCHOTTKY DIODE; Package: D0805
FB1 = FB2: Assembly: NC
FB2 = FB2_1: Assembly: NC
FB3 = FB2_2
G1-G8 G10 = ScrewPad-1P: Assembly: NC; {PCB Footprint}: SCREW9-H3.5-R8
G9 = LOGO-Megawin_3_4: Assembly: NC
Q1 Q3 Q5 Q7 Q9 Q11 Q13 Q15 Q17 Q19 Q21 Q23 = MOS-P-SOT23
R1 = R_1: 2ND PART FIELD: SMD_0805; Package: 0603 SMD Resister
R2 = R_3: Package: 0603 SMD Resister
R3 = R: Package: 0603 SMD Resister
R4 = R_2
R5 = R_4
TP1-TP6 = TPH-GND: Assembly: NC; Package: Gold Test Pin
UP1 = ICP-AP1117: Function: +3.3V Regulator; Package: SOT-223
D4-D118 = DIODE
HK1-HK3 Logo1 Mute1 = SW-PB-4P2
SW1 = SW-PB-2P-KB_111: Function: Prof
SW2 = SW-PB-2P-KB_82: Function: ESC
SW3 = SW-PB-2P-KB_51: Function: F1
SW4 = SW-PB-2P-KB_25: Function: F2
SW5 = SW-PB-2P-KB_5: Function: F3
SW6 = SW-PB-2P-KB_87: Function: F4
SW7 = SW-PB-2P-KB_57: Function: F5
SW8 = SW-PB-2P-KB_29: Function: F6
SW9 = SW-PB-2P-KB_9: Function: F7
SW10 = SW-PB-2P-KB_95: Function: F8
SW11 = SW-PB-2P-KB_64: Function: F9
SW12 = SW-PB-2P-KB_99: Function: M1
SW13 = SW-PB-2P-KB_70: Function: `~
SW14 = SW-PB-2P-KB_40: Function: 1
SW15 = SW-PB-2P-KB_18: Function: 2
SW16 = SW-PB-2P-KB_110: Function: 3
SW17 = SW-PB-2P-KB_81: Function: 4
SW18 = SW-PB-2P-KB_50: Function: 5
SW19 = SW-PB-2P-KB_24: Function: 6
SW20 = SW-PB-2P-KB_4: Function: 7
SW21 = SW-PB-2P-KB_86: Function: 8
SW22 = SW-PB-2P-KB_56: Function: 9
SW23 = SW-PB-2P-KB_109: Function: M2
SW24 = SW-PB-2P-KB_80: Function: TAB
SW25 = SW-PB-2P-KB_48: Function: Q
SW26 = SW-PB-2P-KB_22: Function: W
SW27 = SW-PB-2P-KB_2: Function: E
SW28 = SW-PB-2P-KB_85: Function: R
SW29 = SW-PB-2P-KB_55: Function: T
SW30 = SW-PB-2P-KB_28: Function: Y
SW31 = SW-PB-2P-KB_8: Function: U
SW32 = SW-PB-2P-KB_94: Function: I
SW33 = SW-PB-2P-KB_63: Function: O
SW34 = SW-PB-2P-KB_98: Function: M3
SW35 = SW-PB-2P-KB_68: Function: Caps
SW36 = SW-PB-2P-KB_38: Function: A
SW37 = SW-PB-2P-KB_16: Function: S
SW38 = SW-PB-2P-KB_107: Function: D48
SW39 = SW-PB-2P-KB_78: Function: F
SW40 = SW-PB-2P-KB_47: Function: G
SW41 = SW-PB-2P-KB_21: Function: H
SW42 = SW-PB-2P-KB_1: Function: J
SW43 = SW-PB-2P-KB_84: Function: K
SW44 = SW-PB-2P-KB_54: Function: L
SW45 = SW-PB-2P-KB_96: Function: M4
SW46 = SW-PB-2P-KB_65: Function: L-SH
SW47 = SW-PB-2P-KB_34: Function: Z
SW48 = SW-PB-2P-KB_11: Function: X1
SW49 = SW-PB-2P-KB_97: Function: C
SW50 = SW-PB-2P-KB_67: Function: V
SW51 = SW-PB-2P-KB_37: Function: B
SW52 = SW-PB-2P-KB_20: Function: N1
SW53 = SW-PB-2P-KB_106: Function: M5
SW54 = SW-PB-2P-KB_77: Function: ,<
SW55 = SW-PB-2P-KB_45: Function: M6
SW56 = SW-PB-2P-KB_19: Function: L-CTR
SW57 = SW-PB-2P-KB_105: Function: L-WIN
SW58 = SW-PB-2P-KB_76: Function: L-ALT
SW59 = SW-PB-2P-KB_46: Function: Space
SW60 = SW-PB-2P-KB_27: Function: R-ALT
SW61 = SW-PB-2P-KB_61: Function: F10
SW62 = SW-PB-2P-KB_32: Function: F11
SW63 = SW-PB-2P-KB_15: Function: F12
SW64 = SW-PB-2P-KB_102: Function: PrS
SW65 = SW-PB-2P-KB_74: Function: ScrLock
SW66 = SW-PB-2P-KB_44: Function: PBack
SW67 = SW-PB-2P-KB_92: Function: 0
SW68 = SW-PB-2P-KB_60: Function: -_
SW69 = SW-PB-2P-KB_36: Function: +=
SW70 = SW-PB-2P-KB_13: Function: BackSpace
SW71 = SW-PB-2P-KB_101: Function: Insert
SW72 = SW-PB-2P-KB_72: Function: Home
SW73 = SW-PB-2P-KB_42: Function: PU
SW74 = SW-PB-2P-KB_104: Function: N_/
SW75 = SW-PB-2P-KB_83: Function: N_*
SW76 = SW-PB-2P-KB_52: Function: N_-
SW77 = SW-PB-2P-KB_88: Function: P
SW78 = SW-PB-2P-KB_58: Function: [
SW79 = SW-PB-2P-KB_30: Function: ]
SW80 = SW-PB-2P-KB_6: Function: \
SW81 = SW-PB-2P-KB_91: Function: Delete
SW82 = SW-PB-2P-KB_66: Function: End
SW83 = SW-PB-2P-KB_35: Function: PD
SW84 = SW-PB-2P-KB_12: Function: NumL
SW85 = SW-PB-2P-KB_100: Function: N_8
SW86 = SW-PB-2P-KB_71: Function: N_9
SW87 = SW-PB-2P-KB_41: Function: N_+
SW88 = SW-PB-2P-KB_53: Function: ;:
SW89 = SW-PB-2P-KB_26: Function: '"
SW90 = SW-PB-2P-KB: Function: Enter
SW91 = SW-PB-2P-KB_49: Function: N_7
SW92 = SW-PB-2P-KB_23: Function: N_5
SW93 = SW-PB-2P-KB_3: Function: N_6
SW94 = SW-PB-2P-KB_73: Function: .>
SW95 = SW-PB-2P-KB_43: Function: /?
SW96 = SW-PB-2P-KB_75: Function: R-SH
SW97 = SW-PB-2P-KB_69: Function: UP-L
SW98 = SW-PB-2P-KB_39: Function: N_4
SW99 = SW-PB-2P-KB_17: Function: N_2
SW100 = SW-PB-2P-KB_108: Function: N_3
SW101 = SW-PB-2P-KB_79: Function: N_Enter
SW102 = SW-PB-2P-KB_90: Function: FN
SW103 = SW-PB-2P-KB_59: Function: APP
SW104 = SW-PB-2P-KB_31: Function: R-CTR
SW105 = SW-PB-2P-KB_7: Function: Left-L
SW106 = SW-PB-2P-KB_93: Function: Down-L
SW107 = SW-PB-2P-KB_62: Function: Right-L
SW108 = SW-PB-2P-KB_33: Function: N_1
SW109 = SW-PB-2P-KB_10: Function: N_0
SW110 = SW-PB-2P-KB_103: Function: N_DEL
SW112 = SW-PB-2P-KB_14: Assembly: NC; Function: Space
SW113 = SW-PB-2P-KB_89: Assembly: NC; Function: Space
DD1-DD18 = LED-4P-CRGB3
KD1-KD110 = LED-4P-CRGB: Package: Tri_LED
LED1-LED6 = LED-4P-CRGB2
Q2 Q4 Q6 Q8 Q10 Q12 Q14 Q16 Q18 Q20 Q22 = MOS-N-SOT23
R6-R60 R64-R80 R83 R85 R87-R89 R91-R98 R103-R106 R110-R126 = RES
C6 = CAP-NP_49: Package: 0603 Multilayer Ceramic Chip Capacitor
C7 = CAP-NP_55: Package: 0603 Multilayer Ceramic Chip Capacitor
C8 = CAP-NP_17: Package: 0603 Multilayer Ceramic Chip Capacitor
C9 = CAP-NP_30: Package: 0603 Multilayer Ceramic Chip Capacitor
C10 = CAP-NP_1: Package: 0603 Multilayer Ceramic Chip Capacitor
C11 = CAP-NP: Package: 0603 Multilayer Ceramic Chip Capacitor
C12 = CAP-NP_4: Package: 0603 Multilayer Ceramic Chip Capacitor
C13 = CAP-NP_3: Package: 0603 Multilayer Ceramic Chip Capacitor
C14 = CAP-NP_7: Package: 0603 Multilayer Ceramic Chip Capacitor
C15 = CAP-NP_6: Package: 0603 Multilayer Ceramic Chip Capacitor
C16 = CAP-NP_11: Package: 0603 Multilayer Ceramic Chip Capacitor
C17 = CAP-NP_9: Package: 0603 Multilayer Ceramic Chip Capacitor
C18 = CAP-NP_18: Package: 0603 Multilayer Ceramic Chip Capacitor
C19 = CAP-NP_14: Package: 0603 Multilayer Ceramic Chip Capacitor
C20 = CAP-NP_21: Package: 0603 Multilayer Ceramic Chip Capacitor
C21 = CAP-NP_19: Package: 0603 Multilayer Ceramic Chip Capacitor
C22 = CAP-NP_23: Package: 0603 Multilayer Ceramic Chip Capacitor
C23 = CAP-NP_38: Package: 0603 Multilayer Ceramic Chip Capacitor
C24 = CAP-NP_32: Package: 0603 Multilayer Ceramic Chip Capacitor
C25 = CAP-NP_2: Package: 0603 Multilayer Ceramic Chip Capacitor
C26 = CAP-NP_45: Package: 0603 Multilayer Ceramic Chip Capacitor
C27 = CAP-NP_35: Package: 0603 Multilayer Ceramic Chip Capacitor
C28 = CAP-NP_34: Package: 0603 Multilayer Ceramic Chip Capacitor
C29 = CAP-NP_37: Package: 0603 Multilayer Ceramic Chip Capacitor
C30 = CAP-NP_36: Package: 0603 Multilayer Ceramic Chip Capacitor
C31 = CAP-NP_42: Package: 0603 Multilayer Ceramic Chip Capacitor
C32 = CAP-NP_41: Package: 0603 Multilayer Ceramic Chip Capacitor
C33 = CAP-NP_44: Package: 0603 Multilayer Ceramic Chip Capacitor
C34 = CAP-NP_43: Package: 0603 Multilayer Ceramic Chip Capacitor
C35 = CAP-NP_51: Package: 0603 Multilayer Ceramic Chip Capacitor
C36 = CAP-NP_46
C37 = CAP-NP_47: Package: 0603 Multilayer Ceramic Chip Capacitor
C38 = CAP-NP_53: Package: 0603 Multilayer Ceramic Chip Capacitor
C39 = CAP-NP_52: Package: 0603 Multilayer Ceramic Chip Capacitor
C40 = CAP-NP_54: Package: 0603 Multilayer Ceramic Chip Capacitor
C41 = CAP-NP_16: Package: 0603 Multilayer Ceramic Chip Capacitor
C42 = CAP-NP_8: Package: 0603 Multilayer Ceramic Chip Capacitor
C43 = CAP-NP_26: Package: 0603 Multilayer Ceramic Chip Capacitor
C44 = CAP-NP_40: Package: 0603 Multilayer Ceramic Chip Capacitor
C45 = CAP-NP_12: Package: 0603 Multilayer Ceramic Chip Capacitor
C46 = CAP-NP_10: Package: 0603 Multilayer Ceramic Chip Capacitor
C47 = CAP-NP_15: Package: 0603 Multilayer Ceramic Chip Capacitor
C48 = CAP-NP_13: Package: 0603 Multilayer Ceramic Chip Capacitor
C49 = CAP-NP_22: Package: 0603 Multilayer Ceramic Chip Capacitor
C50 = CAP-NP_20: Package: 0603 Multilayer Ceramic Chip Capacitor
C51 = CAP-NP_25: Package: 0603 Multilayer Ceramic Chip Capacitor
C52 = CAP-NP_24: Package: 0603 Multilayer Ceramic Chip Capacitor
C53 = CAP-NP_28: Package: 0603 Multilayer Ceramic Chip Capacitor
C54 = CAP-NP_27: Package: 0603 Multilayer Ceramic Chip Capacitor
C55 = CAP-NP_31: Package: 0603 Multilayer Ceramic Chip Capacitor
C56 = CAP-NP_29: Package: 0603 Multilayer Ceramic Chip Capacitor
C57 = CAP-NP_33: Package: 0603 Multilayer Ceramic Chip Capacitor
C58 = CAP-NP_50: Assembly: NC
C59 = CAP-NP_48: Assembly: NC; Package: 0603 Multilayer Ceramic Chip Capacitor
C60 = CAP-NP_5: Assembly: NC; Package: 0603 Multilayer Ceramic Chip Capacitor
C61 = CAP-NP_39: Assembly: NC; Package: 0603 Multilayer Ceramic Chip Capacitor
CN1 = HEADER20X2: Function: MCU Module IF-1; Package: HEADER20X2-2.54
CN2 = HEADER22X2: Function: MCU Module IF-2; Package: HEADER22X2-2.54
CN3 = SIP6: Assembly: NC; Function: SWD Connector; Package: SIP6-2.54/Femail
CN4 = HEADER3: 2ND PART FIELD: Pitch 2.54mm; Assembly: NC; Function: ARGB-URT CON; Package: Pitch 2.54mm/Female
CN5 = SIP4: Assembly: NC; Package: SIP4-2.54
CN6 = HEADER3_1: 2ND PART FIELD: Pitch 2.54mm; Assembly: NC; Function: ARGB-URT CON; Package: Pitch 2.54mm/Female
D119-D122 = LED: ATHEROS KEY: 127-00026-000; AtherosDescription: LED, THRU_HOLE,GREEN,3.0MM RADIAL; CISPartType: Diodes\LED
D123 = DIODE-SCHOTTKY-2: Assembly: NC; Function: SCHOTTKY DIODE; Package: D0805
FB4 = FB2
JP1 = JUMPER: Assembly: NC; Package: SIP2-RES
R61 = R_5: Package: R0603
R62 = R_12: Package: R0603
R63 = R_4: Package: R0603
R81 R130 = RES: Assembly: NC
R82 = R_2: Package: R0603
R84 = R_3: 2ND PART FIELD: SMD_0805; Assembly: NC; Package: 0603 SMD Resister
R86 = R: 2ND PART FIELD: SMD_0805; Assembly: NC; Package: 0603 SMD Resister
R90 R99 R107 R108 = R2X
R100 = R_8: Assembly: NC; Package: R0603
R101 = R_10: Package: R0603
R102 = R_1: Assembly: NC; Package: R0603
R109 = R_11: Package: R0603
R127 = R_6: Assembly: NC; Package: 0603 SMD Resister
R128 = R_9: Assembly: NC; Package: 0603 SMD Resister
R129 = R_7: Assembly: NC; Package: 0603 SMD Resister
SW111 = SW-PB-4P: Assembly: NC; Function: Reset
U1 U2 U4 = IC-TLC5948A: Alternate: /MBI5042; Function: LED_Driver
U3 = ICM-25LXX: Function: SPI Flash

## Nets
+3V3: CN2.1 D3.2(CATHODE) D119.1(A) D120.1(A) D121.1(A) D122.1(A) FB2.2 FB3.1 FB4.2 Q1.2(S) R3.2 R6.1 R11.1 R16.1 R21.1 R26.1 R31.1 R36.1 R41.1 R46.1 R51.1 R56.1
+3V3_FS: C36.1 FB4.1 R100.1 R101.1 R102.1 U3.8(VDD)
+3V3_LDO: C5.1 D3.1(ANODE) R4.1 UP1.2(OUT) UP1.4(VOUT)
+5V: C3.1 C4.1 CN1.2 D2.2(CATHODE) FB1.1 R1.1 UP1.3(IN)
+5V_USB: C2.1 CJ1.1(USB_PWR) D2.1(ANODE)
+VDD_DRV: C1.1 C6.1 C23.1 C41.1 FB2.1 Q1.3(D) R61.1 R62.1 R63.1 R82.1 R109.1 U1.24(VDD) U2.24(VDD) U4.24(VDD)
+VDD_LED: C58.1 CN3.4 CN4.1 CN6.1 D123.1(ANODE) FB1.2 FB3.2 Q3.2(S) Q5.2(S) Q7.2(S) Q9.2(S) Q11.2(S) Q13.2(S) Q15.2(S) Q17.2(S) Q19.2(S) Q21.2(S) Q23.2(S) R7.1 R12.1 R17.1 R22.1 R27.1 R32.1 R37.1 R42.1 R47.1 R52.1 R57.1
+VDD_UART0: C59.1 CN5.1 D123.2(CATHODE)
GND: C1.2 C2.2 C3.2 C4.2 C5.2 C6.2 C7.2 C8.2 C9.2 C10.2 C11.2 C12.2 C13.2 C14.2 C15.2 C16.2 C17.2 C18.2 C19.2 C20.2 C21.2 C22.2 C23.2 C24.2 C25.2 C26.2 C27.2 C28.2 C29.2 C30.2 C31.2 C32.2 C33.2 C34.2 C35.2 C36.2 C37.2 C38.2 C39.2 C40.2 C41.2 C42.2 C43.2 C44.2 C45.2 C46.2 C47.2 C48.2 C49.2 C50.2 C51.2 C52.2 C53.2 C54.2 C55.2 C56.2 C57.2 C58.2 C59.2 C60.2 C61.2 CJ1.4(USB_ID) CJ1.5(USB_GND) CJ1.6(shield_1) CJ1.7(shield_2) CJ1.8(shield_3) CJ1.9(shield_4) CN1.1 CN2.2 CN3.2 CN4.3 CN5.2 CN6.3 D1.2(C) G1.1 G2.1 G3.1 G4.1 G5.1 G6.1 G7.1 G8.1 G10.1 JP1.2 R5.2 R9.1 R14.1 R19.1 R24.1 R29.1 R34.1 R39.1 R44.1 R49.1 R54.1 R59.1 R64.2 R83.2 R110.2 SW111.2 TP1.1 TP2.1 TP3.1 TP4.1 TP5.1 TP6.1 U1.1(GND) U2.1(GND) U3.4(GND) U4.1(GND)
ARGB_0: CN2.26 CN4.2
ARGB_1: CN2.30 CN6.2
CapsLock: CN1.32 R99.2
Game: CN1.30 R108.2
GCLK_0: C24.1 C42.1 CN1.25 R85.2 R111.2
GCLK_1: C7.1 CN1.27 R65.2
KB_C0: CN1.40 D4.2(C) D5.2(C) D6.2(C) D7.2(C) D8.2(C) D9.2(C) D10.2(C) D11.2(C) D12.2(C) D13.2(C) D14.2(C)
KB_C1: CN1.37 D15.2(C) D16.2(C) D17.2(C) D18.2(C) D19.2(C) D20.2(C) D21.2(C) D22.2(C) D23.2(C) D24.2(C) D25.2(C)
KB_C2: CN1.38 D26.2(C) D27.2(C) D28.2(C) D29.2(C) D30.2(C) D31.2(C) D32.2(C) D33.2(C) D34.2(C) D35.2(C) D36.2(C)
KB_C3: CN1.33 D37.2(C) D38.2(C) D39.2(C) D40.2(C) D41.2(C) D42.2(C) D43.2(C) D44.2(C) D45.2(C) D46.2(C) D47.2(C)
KB_C4: CN1.36 D48.2(C) D49.2(C) D50.2(C) D51.2(C) D52.2(C) D53.2(C) D54.2(C) D55.2(C) D56.2(C) D57.2(C)
KB_C5: CN1.35 D58.2(C) D59.2(C) D60.2(C) D61.2(C) D62.2(C) D63.2(C)
KB_C6: CN1.10 D64.2(C) D65.2(C) D66.2(C) D67.2(C) D68.2(C) D69.2(C) D70.2(C) D71.2(C) D72.2(C)
KB_C7: CN1.31 D73.2(C) D74.2(C) D75.2(C) D76.2(C) D77.2(C) D78.2(C) D79.2(C) D80.2(C) D81.2(C) D82.2(C) D83.2(C)
KB_C8: CN2.6 D84.2(C) D85.2(C) D86.2(C) D87.2(C) D88.2(C) D89.2(C) D90.2(C) D91.2(C) D92.2(C) D93.2(C) D94.2(C)
KB_C9: CN2.5 D95.2(C) D96.2(C) D97.2(C) D98.2(C) D99.2(C) D100.2(C)
KB_C10: CN2.4 D101.2(C) D102.2(C) D103.2(C) D104.2(C) D105.2(C) D106.2(C) D107.2(C) D108.2(C)
KB_C11: CN1.39 D109.2(C) D110.2(C) D111.2(C) D112.2(C) D113.2(C) D114.2(C) D115.2(C) D116.2(C) D117.2(C) D118.2(C)
KB_R0: CN2.22 SW1.2 SW12.2 SW23.2 SW34.2 SW45.2 SW55.2 SW61.2 SW67.2 SW77.2 SW88.2 SW94.2 SW102.2
KB_R1: CN2.21 SW2.2 SW13.2 SW24.2 SW35.2 SW46.2 SW56.2 SW62.2 SW68.2 SW78.2 SW89.2 SW95.2
KB_R2: CN2.18 SW3.2 SW14.2 SW25.2 SW36.2 SW57.2 SW63.2 SW69.2 SW79.2 SW103.2
KB_R3: CN2.17 SW4.2 SW15.2 SW26.2 SW37.2 SW47.2 SW58.2 SW70.2 SW80.2 SW90.2 SW96.2 SW104.2
KB_R4: CN2.16 SW5.2 SW16.2 SW27.2 SW38.2 SW48.2 SW64.2 SW71.2 SW81.2 SW105.2
KB_R5: CN2.15 SW6.2 SW17.2 SW28.2 SW39.2 SW49.2 SW65.2 SW72.2 SW82.2 SW97.2 SW106.2
KB_R6: CN2.11 SW7.2 SW18.2 SW29.2 SW40.2 SW50.2 SW59.2 SW66.2 SW73.2 SW83.2 SW107.2 SW112.2 SW113.2
KB_R7: CN2.10 HK1.2 HK1.4 Mute1.2 Mute1.4 SW8.2 SW19.2 SW30.2 SW41.2 SW51.2 SW84.2 SW91.2 SW98.2 SW108.2
KB_R8: CN2.9 HK2.2 HK2.4 SW9.2 SW20.2 SW31.2 SW42.2 SW52.2 SW74.2 SW85.2 SW92.2 SW99.2 SW109.2
KB_R9: CN2.8 HK3.2 HK3.4 SW10.2 SW21.2 SW32.2 SW43.2 SW53.2 SW75.2 SW86.2 SW93.2 SW100.2 SW110.2
KB_R10: CN2.7 Logo1.2 Logo1.4 SW11.2 SW22.2 SW33.2 SW44.2 SW54.2 SW60.2 SW76.2 SW87.2 SW101.2
LE: CN1.34 R61.2 U1.4(LE) U2.4(LE) U4.4(LE)
LED_B0: C48.1 KD11.4(B) KD13.4(B) KD24.4(B) KD33.4(B) KD44.4(B) KD53.4(B) KD63.4(B) KD75.4(B) KD82.4(B) KD92.4(B) KD102.4(B) R117.1
LED_B1: C54.1 KD1.4(B) KD17.4(B) KD28.4(B) KD34.4(B) KD45.4(B) KD58.4(B) KD64.4(B) KD76.4(B) KD87.4(B) KD96.4(B) KD103.4(B) R123.1
LED_B2: C56.1 KD2.4(B) KD18.4(B) KD29.4(B) KD35.4(B) KD46.4(B) KD59.4(B) KD70.4(B) KD77.4(B) KD88.4(B) KD97.4(B) KD104.4(B) R124.2
LED_B3: C49.1 KD3.4(B) KD19.4(B) KD30.4(B) KD36.4(B) KD52.4(B) KD60.4(B) KD71.4(B) KD78.4(B) KD89.4(B) KD98.4(B) KD105.4(B) R118.2
LED_B4: C44.1 KD4.4(B) KD20.4(B) KD37.4(B) KD47.4(B) KD61.4(B) KD72.4(B) KD79.4(B) KD90.4(B) KD99.4(B) KD108.4(B) R112.2
LED_B5: C30.1 KD5.4(B) KD21.4(B) KD31.4(B) KD38.4(B) KD65.4(B) KD109.4(B) R93.1
LED_B6: C37.1 KD6.4(B) KD22.4(B) KD32.4(B) KD48.4(B) KD62.4(B) KD66.4(B) LED1.4(B) LED3.4(B) LED4.4(B) R103.1
LED_B7: C38.1 KD7.4(B) KD14.4(B) KD25.4(B) KD39.4(B) KD49.4(B) KD54.4(B) KD67.4(B) KD83.4(B) KD93.4(B) KD110.4(B) LED2.4(B) R104.2
LED_B8: C31.1 KD8.4(B) KD15.4(B) KD26.4(B) KD40.4(B) KD50.4(B) KD55.4(B) KD68.4(B) KD73.4(B) KD84.4(B) KD94.4(B) KD106.4(B) R94.2
LED_B9: C25.1 KD12.4(B) KD16.4(B) KD41.4(B) KD74.4(B) KD85.4(B) KD95.4(B) R87.2
LED_B10: C13.1 KD9.4(B) KD23.4(B) KD42.4(B) KD56.4(B) KD80.4(B) KD86.4(B) KD100.4(B) KD107.4(B) R71.1
LED_B11: C18.1 KD10.4(B) KD27.4(B) KD43.4(B) KD51.4(B) KD57.4(B) KD69.4(B) KD81.4(B) KD91.4(B) KD101.4(B) LED5.4(B) R77.1
LED_B12: C20.1 DD1.4(B) DD2.4(B) DD3.4(B) LED6.4(B) R78.2
LED_B13: C15.1 DD5.4(B) DD6.4(B) DD8.4(B) DD10.4(B) DD12.4(B) DD14.4(B) R72.2
LED_B14: C9.1 DD4.4(B) DD7.4(B) DD9.4(B) DD11.4(B) DD13.4(B) DD15.4(B) DD16.4(B) DD17.4(B) DD18.4(B) R66.2
LED_G0: C46.1 KD11.3(G) KD13.3(G) KD24.3(G) KD33.3(G) KD44.3(G) KD53.3(G) KD63.3(G) KD75.3(G) KD82.3(G) KD92.3(G) KD102.3(G) R115.1
LED_G1: C51.1 KD1.3(G) KD17.3(G) KD28.3(G) KD34.3(G) KD45.3(G) KD58.3(G) KD64.3(G) KD76.3(G) KD87.3(G) KD96.3(G) KD103.3(G) R121.1
LED_G2: C57.1 KD2.3(G) KD18.3(G) KD29.3(G) KD35.3(G) KD46.3(G) KD59.3(G) KD70.3(G) KD77.3(G) KD88.3(G) KD97.3(G) KD104.3(G) R126.2
LED_G3: C52.1 KD3.3(G) KD19.3(G) KD30.3(G) KD36.3(G) KD52.3(G) KD60.3(G) KD71.3(G) KD78.3(G) KD89.3(G) KD98.3(G) KD105.3(G) R120.2
LED_G4: C45.1 KD4.3(G) KD20.3(G) KD37.3(G) KD47.3(G) KD61.3(G) KD72.3(G) KD79.3(G) KD90.3(G) KD99.3(G) KD108.3(G) R114.2
LED_G5: C28.1 KD5.3(G) KD21.3(G) KD31.3(G) KD38.3(G) KD65.3(G) KD109.3(G) R91.1
LED_G6: C34.1 KD6.3(G) KD22.3(G) KD32.3(G) KD48.3(G) KD62.3(G) KD66.3(G) LED1.3(G) LED3.3(G) LED4.3(G) R97.1
LED_G7: C40.1 KD7.3(G) KD14.3(G) KD25.3(G) KD39.3(G) KD49.3(G) KD54.3(G) KD67.3(G) KD83.3(G) KD93.3(G) KD110.3(G) LED2.3(G) R106.2
LED_G8: C33.1 KD8.3(G) KD15.3(G) KD26.3(G) KD40.3(G) KD50.3(G) KD55.3(G) KD68.3(G) KD73.3(G) KD84.3(G) KD94.3(G) KD106.3(G) R96.2
LED_G9: C27.1 KD12.3(G) KD16.3(G) KD41.3(G) KD74.3(G) KD85.3(G) KD95.3(G) R89.2
LED_G10: C11.1 KD9.3(G) KD23.3(G) KD42.3(G) KD56.3(G) KD80.3(G) KD86.3(G) KD100.3(G) KD107.3(G) R69.1
LED_G11: C17.1 KD10.3(G) KD27.3(G) KD43.3(G) KD51.3(G) KD57.3(G) KD69.3(G) KD81.3(G) KD91.3(G) KD101.3(G) LED5.3(G) R75.1
LED_G12: C22.1 DD1.3(G) DD2.3(G) DD3.3(G) LED6.3(G) R80.2
LED_G13: C16.1 DD5.3(G) DD6.3(G) DD8.3(G) DD10.3(G) DD12.3(G) DD14.3(G) R74.2
LED_G14: C10.1 DD4.3(G) DD7.3(G) DD9.3(G) DD11.3(G) DD13.3(G) DD15.3(G) DD16.3(G) DD17.3(G) DD18.3(G) R68.2
LED_PW: CN2.29 R2.1
LED_R0: C43.1 KD11.2(R) KD13.2(R) KD24.2(R) KD33.2(R) KD44.2(R) KD53.2(R) KD63.2(R) KD75.2(R) KD82.2(R) KD92.2(R) KD102.2(R) R113.1
LED_R1: C50.1 KD1.2(R) KD17.2(R) KD28.2(R) KD34.2(R) KD45.2(R) KD58.2(R) KD64.2(R) KD76.2(R) KD87.2(R) KD96.2(R) KD103.2(R) R119.1
LED_R2: C55.1 KD2.2(R) KD18.2(R) KD29.2(R) KD35.2(R) KD46.2(R) KD59.2(R) KD70.2(R) KD77.2(R) KD88.2(R) KD97.2(R) KD104.2(R) R125.1
LED_R3: C53.1 KD3.2(R) KD19.2(R) KD30.2(R) KD36.2(R) KD52.2(R) KD60.2(R) KD71.2(R) KD78.2(R) KD89.2(R) KD98.2(R) KD105.2(R) R122.2
LED_R4: C47.1 KD4.2(R) KD20.2(R) KD37.2(R) KD47.2(R) KD61.2(R) KD72.2(R) KD79.2(R) KD90.2(R) KD99.2(R) KD108.2(R) R116.2
LED_R5: C26.1 KD5.2(R) KD21.2(R) KD31.2(R) KD38.2(R) KD65.2(R) KD109.2(R) R88.1
LED_R6: C32.1 KD6.2(R) KD22.2(R) KD32.2(R) KD48.2(R) KD62.2(R) KD66.2(R) LED1.2(R) LED3.2(R) LED4.2(R) R95.1
LED_R7: C39.1 KD7.2(R) KD14.2(R) KD25.2(R) KD39.2(R) KD49.2(R) KD54.2(R) KD67.2(R) KD83.2(R) KD93.2(R) KD110.2(R) LED2.2(R) R105.1
LED_R8: C35.1 KD8.2(R) KD15.2(R) KD26.2(R) KD40.2(R) KD50.2(R) KD55.2(R) KD68.2(R) KD73.2(R) KD84.2(R) KD94.2(R) KD106.2(R) R98.2
LED_R9: C29.1 KD12.2(R) KD16.2(R) KD41.2(R) KD74.2(R) KD85.2(R) KD95.2(R) R92.2
LED_R10: C8.1 KD9.2(R) KD23.2(R) KD42.2(R) KD56.2(R) KD80.2(R) KD86.2(R) KD100.2(R) KD107.2(R) R67.1
LED_R11: C14.1 KD10.2(R) KD27.2(R) KD43.2(R) KD51.2(R) KD57.2(R) KD69.2(R) KD81.2(R) KD91.2(R) KD101.2(R) LED5.2(R) R73.1
LED_R12: C21.1 DD1.2(R) DD2.2(R) DD3.2(R) LED6.2(R) R79.1
LED_R13: C19.1 DD5.2(R) DD6.2(R) DD8.2(R) DD10.2(R) DD12.2(R) DD14.2(R) R76.2
LED_R14: C12.1 DD4.2(R) DD7.2(R) DD9.2(R) DD11.2(R) DD13.2(R) DD15.2(R) DD16.2(R) DD17.2(R) DD18.2(R) R70.2
LED_Y0: CN2.24 R8.1
LED_Y1: CN2.25 R13.1
LED_Y2: CN1.9 R18.1
LED_Y3: CN1.12 R23.1
LED_Y4: CN1.11 R28.1
LED_Y5: CN1.15 R33.1
LED_Y6: CN1.18 R38.1
LED_Y7: CN1.17 R43.1
LED_Y8: CN1.20 R48.1
LED_Y9: CN1.19 R53.1
LED_Y10: CN2.23 R58.1
MG_DM: CJ1.2(USB_DM) R86.1
MG_DP: CJ1.3(USB_DP) R84.1
MG_PA2: CN1.28 R90.2
MG_PA5: CN1.29 R107.2
MG_PB0: CN2.40 R101.2 U3.1(CE#)
MG_PB1: CN2.39 R130.1 U3.2(SO/D1)
MG_PB2: CN2.38 R62.2 U1.3(DCLK) U2.3(DCLK) U3.6(SCK) U4.3(DCLK)
MG_PB3: CN2.37 R81.1 R109.2 U3.5(D0/SI) U4.2(SDI)
MG_PB4: CN2.32 R102.2 U3.7(D3/RST)
MG_PB5: CN2.31 R100.2 U3.3(WP/D2)
MG_PB8: CN2.28 R129.2
MG_PB9: CN2.27 R128.2
MG_PC4: CN2.14 CN3.5
MG_PC5: CN2.13 CN3.3
MG_PC6: CN2.12 R127.2 SW111.1
MG_PD4: CN1.14 R86.2
MG_PD5: CN1.13 R84.2
SDO_0: R82.2 U2.2(SDI) U4.22(SDO)
SDO_1: R63.2 R81.2 U1.2(SDI) U2.22(SDO)
SDO_2: R130.2 U1.22(SDO)
SWSRST: CN3.1 JP1.1 R127.1
U5V0_RXD: C61.1 CN5.3 R128.1
U5V0_TXD: C60.1 CN5.4 R129.1
V_1: DD1.1(C) KD1.1(V) KD2.1(V) KD3.1(V) KD4.1(V) KD5.1(V) KD6.1(V) KD7.1(V) KD8.1(V) KD9.1(V) KD10.1(V) KD11.1(V) KD12.1(V) R10.2
V_2: DD2.1(C) KD13.1(V) KD14.1(V) KD15.1(V) KD16.1(V) KD17.1(V) KD18.1(V) KD19.1(V) KD20.1(V) KD21.1(V) KD22.1(V) KD23.1(V) R15.2
V_3: DD3.1(C) DD4.1(C) DD5.1(C) KD24.1(V) KD25.1(V) KD26.1(V) KD27.1(V) KD28.1(V) KD29.1(V) KD30.1(V) KD31.1(V) KD32.1(V) R20.2
V_4: DD6.1(C) DD7.1(C) KD33.1(V) KD34.1(V) KD35.1(V) KD36.1(V) KD37.1(V) KD38.1(V) KD39.1(V) KD40.1(V) KD41.1(V) KD42.1(V) KD43.1(V) R25.2
V_5: DD8.1(C) DD9.1(C) KD44.1(V) KD45.1(V) KD46.1(V) KD47.1(V) KD48.1(V) KD49.1(V) KD50.1(V) KD51.1(V) KD52.1(V) R30.2
V_6: DD10.1(C) DD11.1(C) KD53.1(V) KD54.1(V) KD55.1(V) KD56.1(V) KD57.1(V) KD58.1(V) KD59.1(V) KD60.1(V) KD61.1(V) KD62.1(V) R35.2
V_7: DD12.1(C) DD13.1(C) KD63.1(V) KD64.1(V) KD65.1(V) KD66.1(V) KD67.1(V) KD68.1(V) KD69.1(V) KD70.1(V) KD71.1(V) KD72.1(V) R40.2
V_8: DD14.1(C) DD15.1(C) KD73.1(V) KD74.1(V) KD75.1(V) KD76.1(V) KD77.1(V) KD78.1(V) KD79.1(V) KD80.1(V) KD81.1(V) LED1.1(C) LED2.1(C) R45.2
V_9: DD16.1(C) KD82.1(V) KD83.1(V) KD84.1(V) KD85.1(V) KD86.1(V) KD87.1(V) KD88.1(V) KD89.1(V) KD90.1(V) KD91.1(V) LED3.1(C) R50.2
V_10: DD17.1(C) KD92.1(V) KD93.1(V) KD94.1(V) KD95.1(V) KD96.1(V) KD97.1(V) KD98.1(V) KD99.1(V) KD100.1(V) KD101.1(V) LED4.1(C) R55.2
V_11: DD18.1(C) KD102.1(V) KD103.1(V) KD104.1(V) KD105.1(V) KD106.1(V) KD107.1(V) KD108.1(V) KD109.1(V) KD110.1(V) LED5.1(C) LED6.1(C) R60.2
N65646287: R4.2 R5.1 UP1.1(ADJ)
N66677690: Q2.1(G) R6.2
N66677692: Q2.3(D) Q3.1(G) R7.2
N66677769: Q2.2(S) R8.2
N66677923: Q3.3(D) R9.2 R10.1
N66678196: Q4.1(G) R11.2
N66678198: Q4.3(D) Q5.1(G) R12.2
N66678271: Q4.2(S) R13.2
N66678415: Q5.3(D) R14.2 R15.1
N66678688: Q6.1(G) R16.2
N66678690: Q6.3(D) Q7.1(G) R17.2
N66678765: Q6.2(S) R18.2
N66678909: Q7.3(D) R19.2 R20.1
N66679201: Q8.1(G) R21.2
N66679203: Q8.3(D) Q9.1(G) R22.2
N66679280: Q8.2(S) R23.2
N66679434: Q9.3(D) R24.2 R25.1
N66679688: Q10.1(G) R26.2
N66679690: Q10.3(D) Q11.1(G) R27.2
N66679759: Q10.2(S) R28.2
N66679893: Q11.3(D) R29.2 R30.1
N66680166: Q12.1(G) R31.2
N66680168: Q12.3(D) Q13.1(G) R32.2
N66680241: Q12.2(S) R33.2
N66680385: Q13.3(D) R34.2 R35.1
N66680658: Q14.1(G) R36.2
N66680660: Q14.3(D) Q15.1(G) R37.2
N66680733: Q14.2(S) R38.2
N66680877: Q15.3(D) R39.2 R40.1
N66681169: Q16.1(G) R41.2
N66681171: Q16.3(D) Q17.1(G) R42.2
N66681249: Q16.2(S) R43.2
N66681405: Q17.3(D) R44.2 R45.1
N66681678: Q18.1(G) R46.2
N66681680: Q18.3(D) Q19.1(G) R47.2
N66681753: Q18.2(S) R48.2
N66681897: Q19.3(D) R49.2 R50.1
N66682170: Q20.1(G) R51.2
N66682172: Q20.3(D) Q21.1(G) R52.2
N66682247: Q20.2(S) R53.2
N66682395: Q21.3(D) R54.2 R55.1
N66682668: Q22.1(G) R56.2
N66682670: Q22.3(D) Q23.1(G) R57.2
N66682755: Q22.2(S) R58.2
N66682757: Q23.3(D) R59.2 R60.1
N66768139: D118.1(A) Logo1.1 Logo1.3
N66768191: D70.1(A) HK1.1 HK1.3
N66768294: D80.1(A) Mute1.1 Mute1.3
N66768577: D71.1(A) HK2.1 HK2.3
N66768637: D72.1(A) HK3.1 HK3.3
N66793139: D119.2(C) R90.1
N66793165: D120.2(C) R99.1
N66793193: D121.2(C) R107.1
N66793219: D122.2(C) R108.1
N66799673: R64.1 U1.23(R-EXT)
N66799706: R65.1 U1.21(GCLK)
N66799749: R66.1 U1.20(OUT15)
N66799799: R67.2 U1.6(OUT1)
N66799801: R68.1 U1.19(OUT14)
N66799851: R69.2 U1.7(OUT2)
N66799853: R70.1 U1.18(OUT13)
N66799903: R71.2 U1.8(OUT3)
N66799905: R72.1 U1.17(OUT12)
N66799955: R73.2 U1.9(OUT4)
N66799957: R74.1 U1.16(OUT11)
N66800007: R75.2 U1.10(OUT5)
N66800009: R76.1 U1.15(OUT10)
N66800059: R77.2 U1.11(OUT6)
N66800061: R78.1 U1.14(OUT09)
N66800094: R79.2 U1.12(OUT7)
N66800096: R80.1 U1.13(OUT08)
N66800210: R83.1 U2.23(R-EXT)
N66800242: R85.1 U2.21(GCLK)
N66800285: R87.1 U2.20(OUT15)
N66800335: R88.2 U2.6(OUT1)
N66800337: R89.1 U2.19(OUT14)
N66800387: R91.2 U2.7(OUT2)
N66800389: R92.1 U2.18(OUT13)
N66800439: R93.2 U2.8(OUT3)
N66800441: R94.1 U2.17(OUT12)
N66800491: R95.2 U2.9(OUT4)
N66800493: R96.1 U2.16(OUT11)
N66800543: R97.2 U2.10(OUT5)
N66800545: R98.1 U2.15(OUT10)
N66800595: R103.2 U2.11(OUT6)
N66800597: R104.1 U2.14(OUT09)
N66800630: R105.2 U2.12(OUT7)
N66800632: R106.1 U2.13(OUT08)
N66800731: R110.1 U4.23(R-EXT)
N66800763: R111.1 U4.21(GCLK)
N66800806: R112.1 U4.20(OUT15)
N66800856: R113.2 U4.6(OUT1)
N66800858: R114.1 U4.19(OUT14)
N66800908: R115.2 U4.7(OUT2)
N66800910: R116.1 U4.18(OUT13)
N66800960: R117.2 U4.8(OUT3)
N66800962: R118.1 U4.17(OUT12)
N66801012: R119.2 U4.9(OUT4)
N66801014: R120.1 U4.16(OUT11)
N66801064: R121.2 U4.10(OUT5)
N66801066: R122.1 U4.15(OUT10)
N66801116: R123.2 U4.11(OUT6)
N66801118: R124.1 U4.14(OUT09)
N66801151: R125.2 U4.12(OUT7)
N66801153: R126.1 U4.13(OUT08)
N66811019: Q1.1(G) R2.2 R3.1
N66935930: D62.1(A) SW59.1 SW112.1 SW113.1
N67025586: D19.1(A) SW16.1
N67025587: D52.1(A) SW49.1
N67025588: D74.1(A) SW68.1
N67025589: D11.1(A) SW8.1
N67025590: D26.1(A) SW23.1
N67025591: D10.1(A) SW7.1
N67025592: D4.1(A) SW1.1
N67025593: D33.1(A) SW30.1
N67025594: D107.1(A) SW100.1
N67025595: D75.1(A) SW69.1
N67025596: D41.1(A) SW38.1
N67025597: D103.1(A) SW96.1
N67025598: D5.1(A) SW2.1
N67025599: D56.1(A) SW53.1
N67025600: D68.1(A) SW65.1
N67025601: D90.1(A) SW83.1
N67025602: D111.1(A) SW104.1
N67025603: D101.1(A) SW94.1
N67025604: D20.1(A) SW17.1
N67025605: D86.1(A) SW79.1
N67025606: D78.1(A) SW72.1
N67025607: D27.1(A) SW24.1
N67025608: D60.1(A) SW57.1
N67025609: D8.1(A) SW5.1
N67025610: D108.1(A) SW101.1
N67025611: D50.1(A) SW47.1
N67025612: D81.1(A) SW74.1
N67025613: D93.1(A) SW86.1
N67025614: D42.1(A) SW39.1
N67025615: D23.1(A) SW20.1
N67025616: D57.1(A) SW54.1
N67025617: D48.1(A) SW45.1
N67025618: D100.1(A) SW93.1
N67025619: D13.1(A) SW10.1
N67025620: D30.1(A) SW27.1
N67025621: D112.1(A) SW105.1
N67025622: D35.1(A) SW32.1
N67025623: D45.1(A) SW42.1
N67025624: D87.1(A) SW80.1
N67025625: D59.1(A) SW56.1
N67025626: D105.1(A) SW98.1
N67025627: D16.1(A) SW13.1
N67025628: D61.1(A) SW58.1
N67025629: D55.1(A) SW52.1
N67025630: D97.1(A) SW90.1
N67025631: D39.1(A) SW36.1
N67025632: D109.1(A) SW102.1
N67025633: D110.1(A) SW103.1
N67025634: D99.1(A) SW92.1
N67025635: D115.1(A) SW108.1
N67025636: D113.1(A) SW106.1
N67025637: D54.1(A) SW51.1
N67025638: D104.1(A) SW97.1
N67025639: D29.1(A) SW26.1
N67025640: D65.1(A) SW62.1
N67025641: D66.1(A) SW63.1
N67025642: D38.1(A) SW35.1
N67025643: D76.1(A) SW70.1
N67025644: D44.1(A) SW41.1
N67025645: D12.1(A) SW9.1
N67025646: D73.1(A) SW67.1
N67025647: D53.1(A) SW50.1
N67025648: D91.1(A) SW84.1
N67025649: D82.1(A) SW75.1
N67025650: D85.1(A) SW78.1
N67025651: D114.1(A) SW107.1
N67025652: D34.1(A) SW31.1
N67025653: D88.1(A) SW81.1
N67025654: D83.1(A) SW76.1
N67025655: D84.1(A) SW77.1
N67025656: D64.1(A) SW61.1
N67025657: D58.1(A) SW55.1
N67025658: D18.1(A) SW15.1
N67025659: D51.1(A) SW48.1
N67025660: D69.1(A) SW66.1
N67025661: D106.1(A) SW99.1
N67025662: D6.1(A) SW3.1
N67025663: D9.1(A) SW6.1
N67025664: D25.1(A) SW22.1
N67025665: D89.1(A) SW82.1
N67025666: D102.1(A) SW95.1
N67025667: D40.1(A) SW37.1
N67025668: D24.1(A) SW21.1
N67025669: D32.1(A) SW29.1
N67025670: D21.1(A) SW18.1
N67025671: D31.1(A) SW28.1
N67025672: D47.1(A) SW44.1
N67025673: D79.1(A) SW73.1
N67025674: D96.1(A) SW89.1
N67025675: D98.1(A) SW91.1
N67025676: D46.1(A) SW43.1
N67025677: D94.1(A) SW87.1
N67025678: D117.1(A) SW110.1
N67025679: D116.1(A) SW109.1
N67025680: D67.1(A) SW64.1
N67025681: D28.1(A) SW25.1
N67025682: D17.1(A) SW14.1
N67025683: D77.1(A) SW71.1
N67025684: D43.1(A) SW40.1
N67025685: D63.1(A) SW60.1
N67025686: D7.1(A) SW4.1
N67025687: D49.1(A) SW46.1
N67025688: D92.1(A) SW85.1
N67025689: D14.1(A) SW11.1
N67025690: D22.1(A) SW19.1
N67025691: D95.1(A) SW88.1
N67025692: D36.1(A) SW33.1
N67025693: D15.1(A) SW12.1
N67025694: D37.1(A) SW34.1
N67035599: D1.1(A) R1.2

Not connected (* = marked no-connect by the designer): CN1 3* 4* 5* 6* 7* 8* 16* 21* 22* 23* 24* 26*; CN2 3* 19* 20* 33* 34* 35* 36* 41* 42* 43* 44*; CN3 6*; G9 1(.); SW111 3* 4*; U1 5(OUT0)*; U2 5(OUT0)*; U4 5(OUT0)*

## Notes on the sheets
sheet 1
- MG04-05A
- 2021.1
- GR08-2105B
- MG32F02U USB Keyboard
- PCB Screw Position
- USB
- LED Power
- LED Driver IC Power
- Power (3.3V)
- +3V3_LDO about 3.33 volt
- Ra
- *Short these ground planes on PCB
- Rb
- +3V3_LDO=1.25*(1+Rb/Ra)
sheet 4
- D
- C
- MG_PE10
- MG_PE12
- MG_PE11
- MG_PE13
- MG_PC15
- MG_PE14
- MG_PE15
- (MG_DP)
- MG_PD5
- MG_PD4
- (MG_DM)
- MG_PD6
- MG_PE9
- MG_PE8
- MG_PD13
- MG_PD12
- MG_PD15
- MG_PD14
- (TM36_OC10)
- MG_PA0
- (URT1_TX)
- (TM36_OC2N)
- (URT4_RX)
- (URT4_TX)
- (URT2_TX)
- (SPI0_NSS)
- MG_PE3
- MG_PE2
- MG_PE1
- MG_PE0
- A
- B
- MCU Module
- PKT84
- close CN1
- LED Driver
- Keyboard LED
- UART Connector
- LED0
- (Input)
- LED1
- (Output)
- LED2
- LED3
- Chip Reset
- SWD
- ARGB  Connector
- SWD Ground
- SWD Power
- SWD Out
- (PB10) URT1_TX
- JP1 short : Force Reset
- SPI Flash
- (PB6) URT2_TX
sheet 5
- Board Features :
- Layout Rule :
- * MG32F02U Demo Board
- * Impedance :
- * USB Device Interface
- 1. Single-end signals ~ 12 mil/124ohm(Coated MicroStrip) for general nets
  2. Single-end signals ~ 10 mil/129ohm(Coated MicroStrip) for LQFP80
  3. Single-end signals with ground shield ~ 12-6/61ohm(Coated Coplanar Strips)
  4. USB differential signals ~ 15-5-15/90ohm (Edge-Coupled Coated MicroStrip)
- * Key Matrix Keyboard
- * RGB LED Matrix
- * ARGB Interface
- * Power/Ground :
- 1. Bypass cap. need close to related power/ground pin
- 2. Using Copper for DC input source and LDO input/output path
- Power ~
- * USB-Micro Connector
- * Built-in 5V-to-3.3V(VDD) LDO Circuit
- Debug Interface ~
- * SWD IF Connector SIP6-2.54 *1
- Board Note :
- * UART Connector SIP4-2.54 * 2
- * Ferrite Beed Spec :
- Module IF
- FB :     Rdc=0.2 , Z=300/100MHz , Idc=500mA ~ MCB2012S301H
  FB_L : Rdc=0.015 , Z=120/100MHz , Idc=6000mA ~ MHC3216S121W
  FB_S : Rdc=0.25 , Z=60/100MHz , Idc=500mA ~ MCB1608H600H
  FB_0603 :     Rdc=0.15 , Z=120/100MHz , Idc=500mA ~ MCB1608S121H
- * MCU Chip Module Connector 20x2 *1
- On Board Component Circuit
- * SPI Flash SOP
- Others ~
- ECO List on Circuit:
- * Push Button  *1 (Reset )
- 1. Add G10 Screw on PCB left-top corner
- * Key Matrix  * 110
- 2. Fix SW112/SW113 nets/traces missing on PCB(circuit no change)
- * RGB LED *110
- 3. Change CN3/CN5 +VDD net to +VDD_LED
- * Extra Key  *5
- 4. Change CN4/CN6 +5V net to +VDD_LED
- * Around LED *18
- 5. Add R130 and SDO_2 net on U1
- * Extra LED *6
- ECO List on PCB only:
- * User LED *4
- 1. Rotate left 90 degree of SW87(+), SW101(Enter) on MG04-05A PCB
- 2. Change Space key  (SW59) mechanical outline on MG04-05UA PCB
